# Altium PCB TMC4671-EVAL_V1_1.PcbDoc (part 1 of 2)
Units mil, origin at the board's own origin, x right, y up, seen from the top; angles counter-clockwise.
Board outline 2165.36 x 3346.46 mil, 6 copper layers (Top, GND1, MID, VM, GND2, Bottom), stack 61.733 mil thick; 157 components, 127 nets, 622 pads, 423 vias.
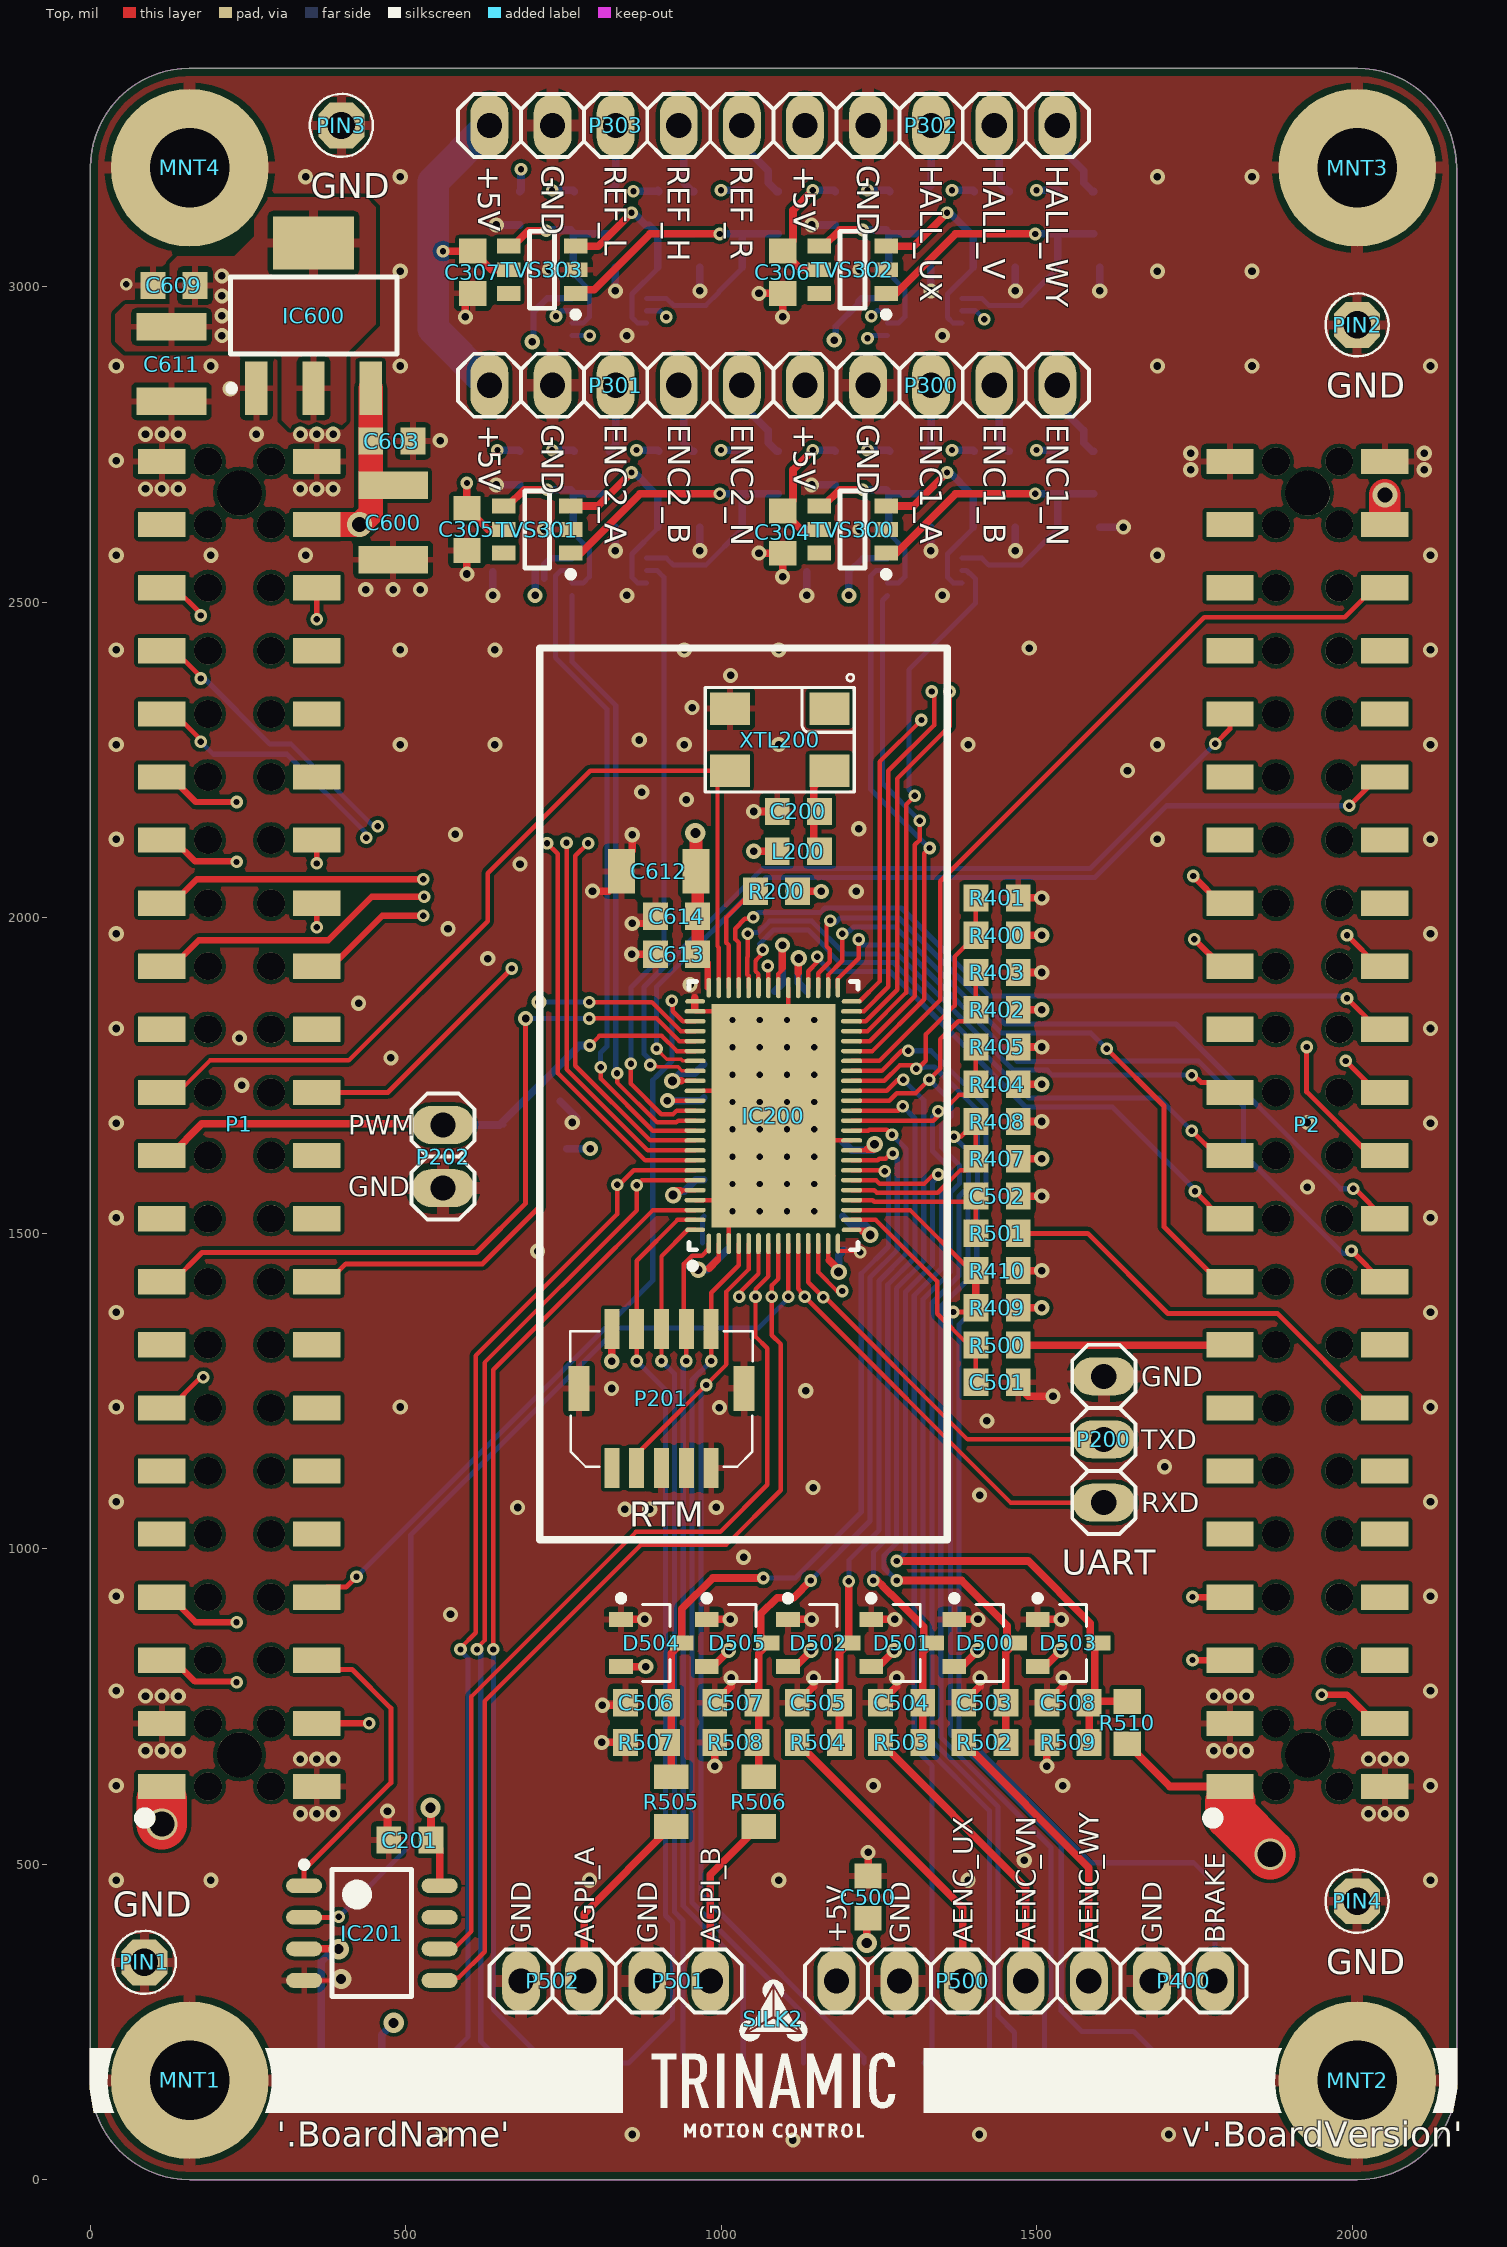
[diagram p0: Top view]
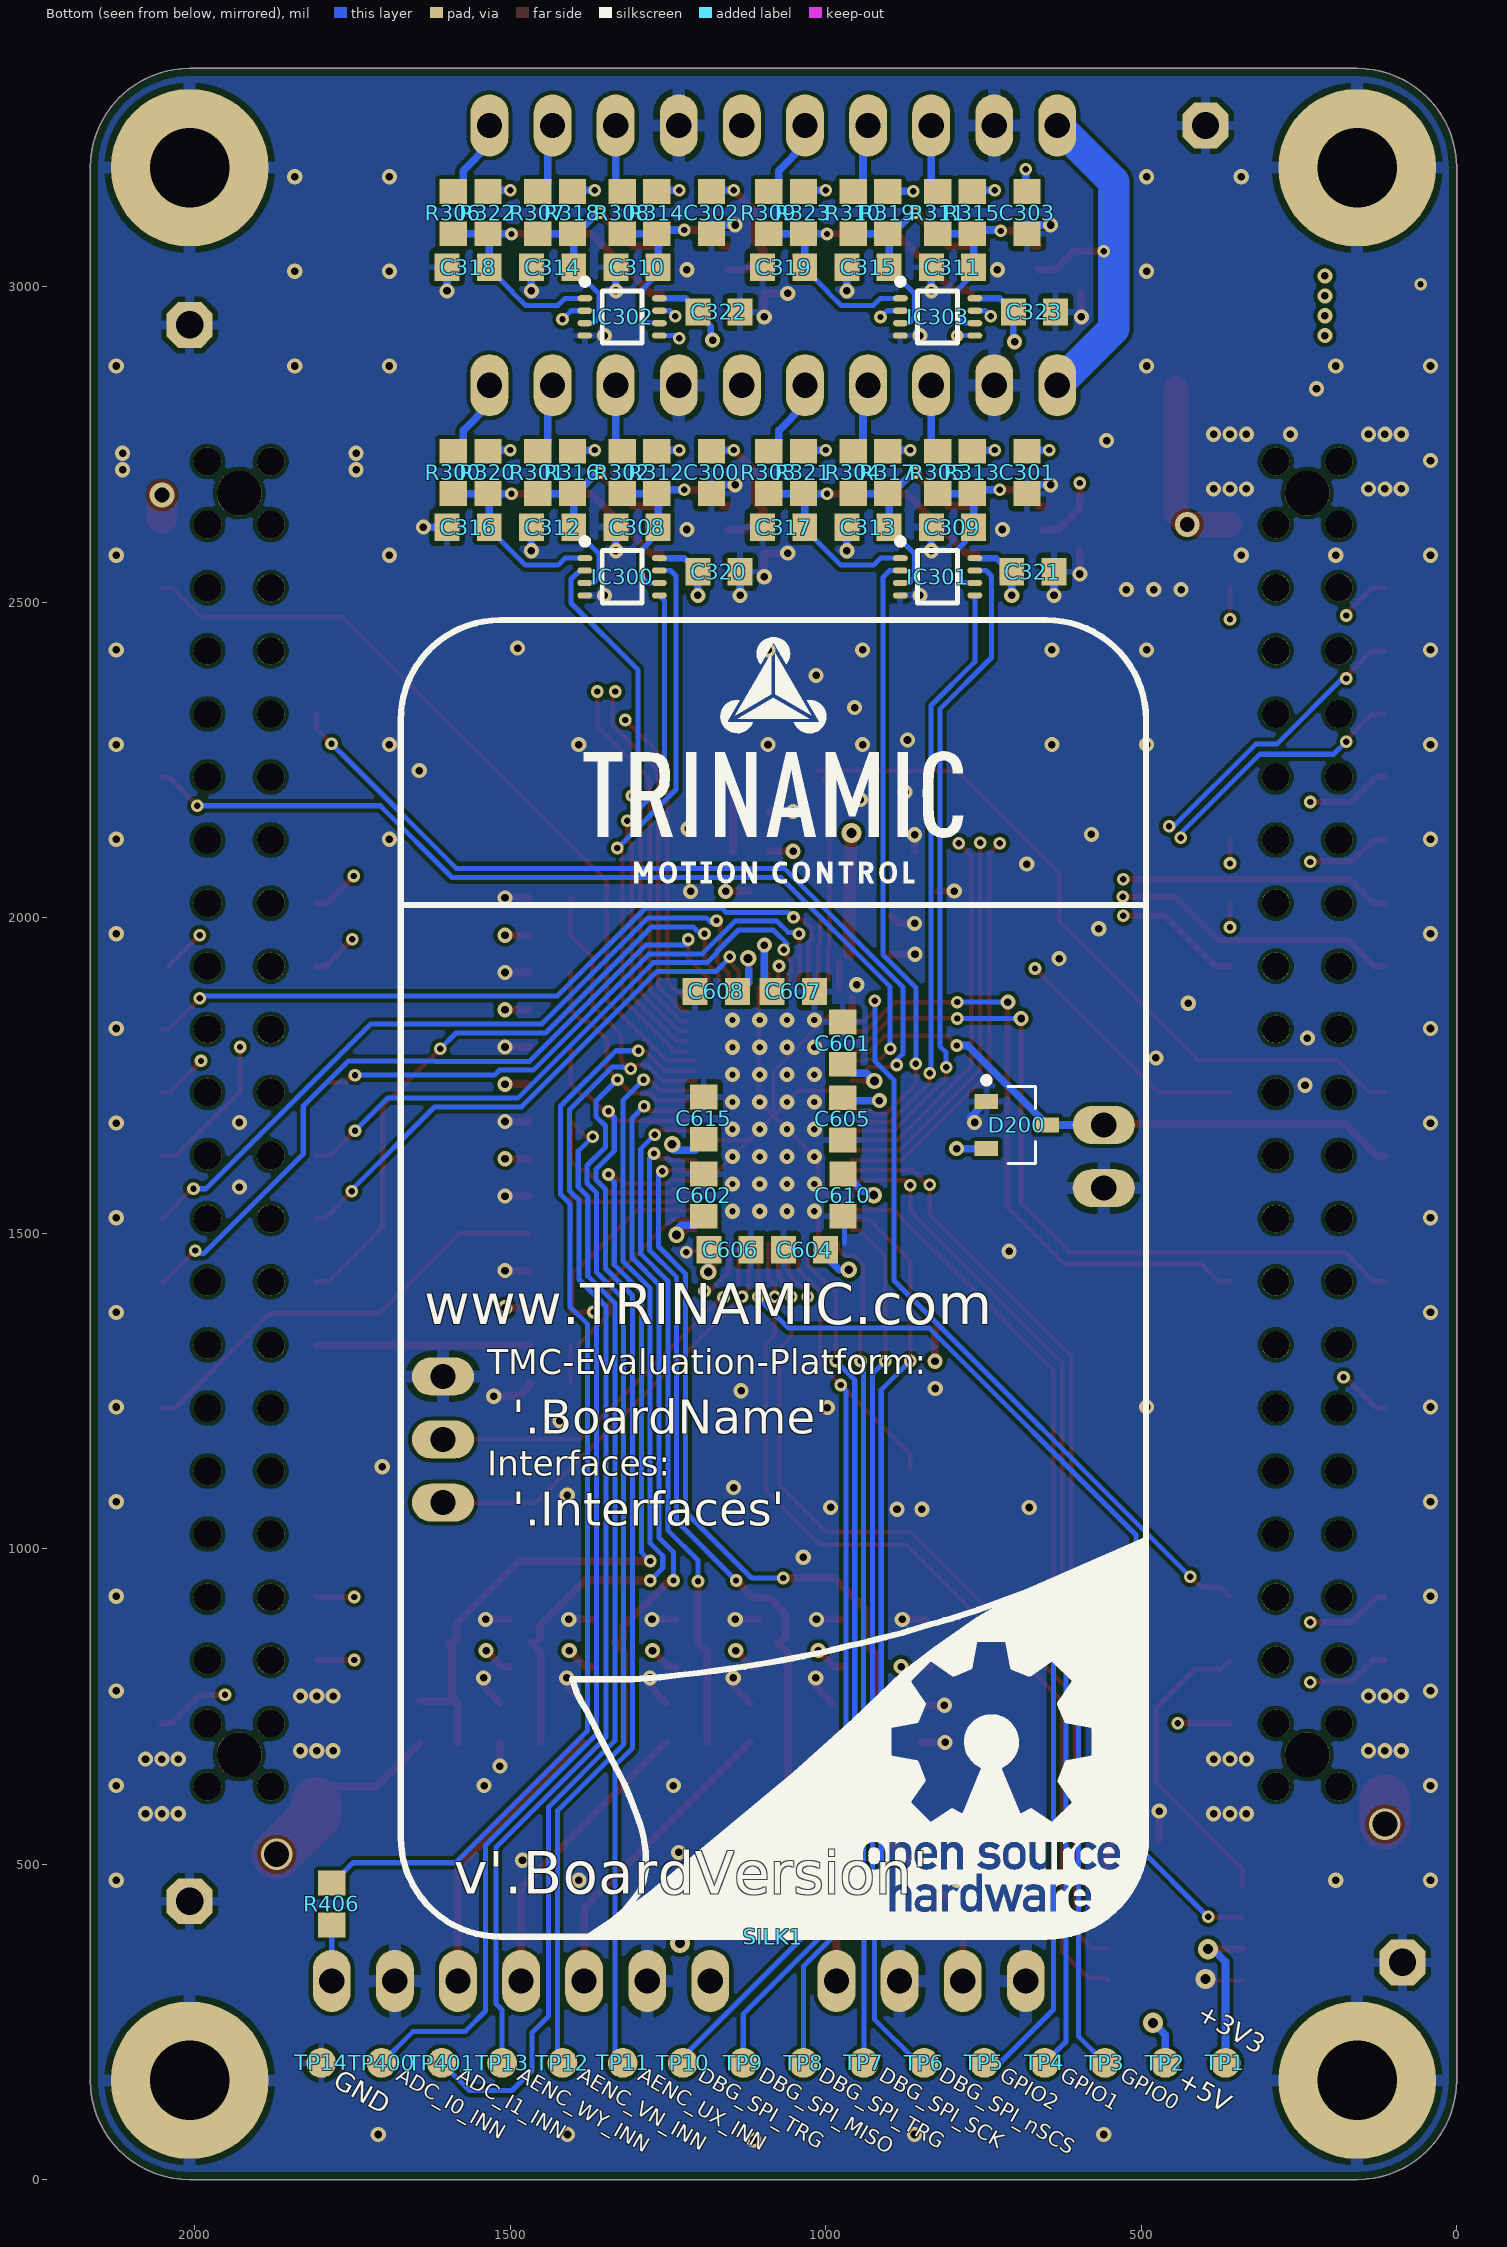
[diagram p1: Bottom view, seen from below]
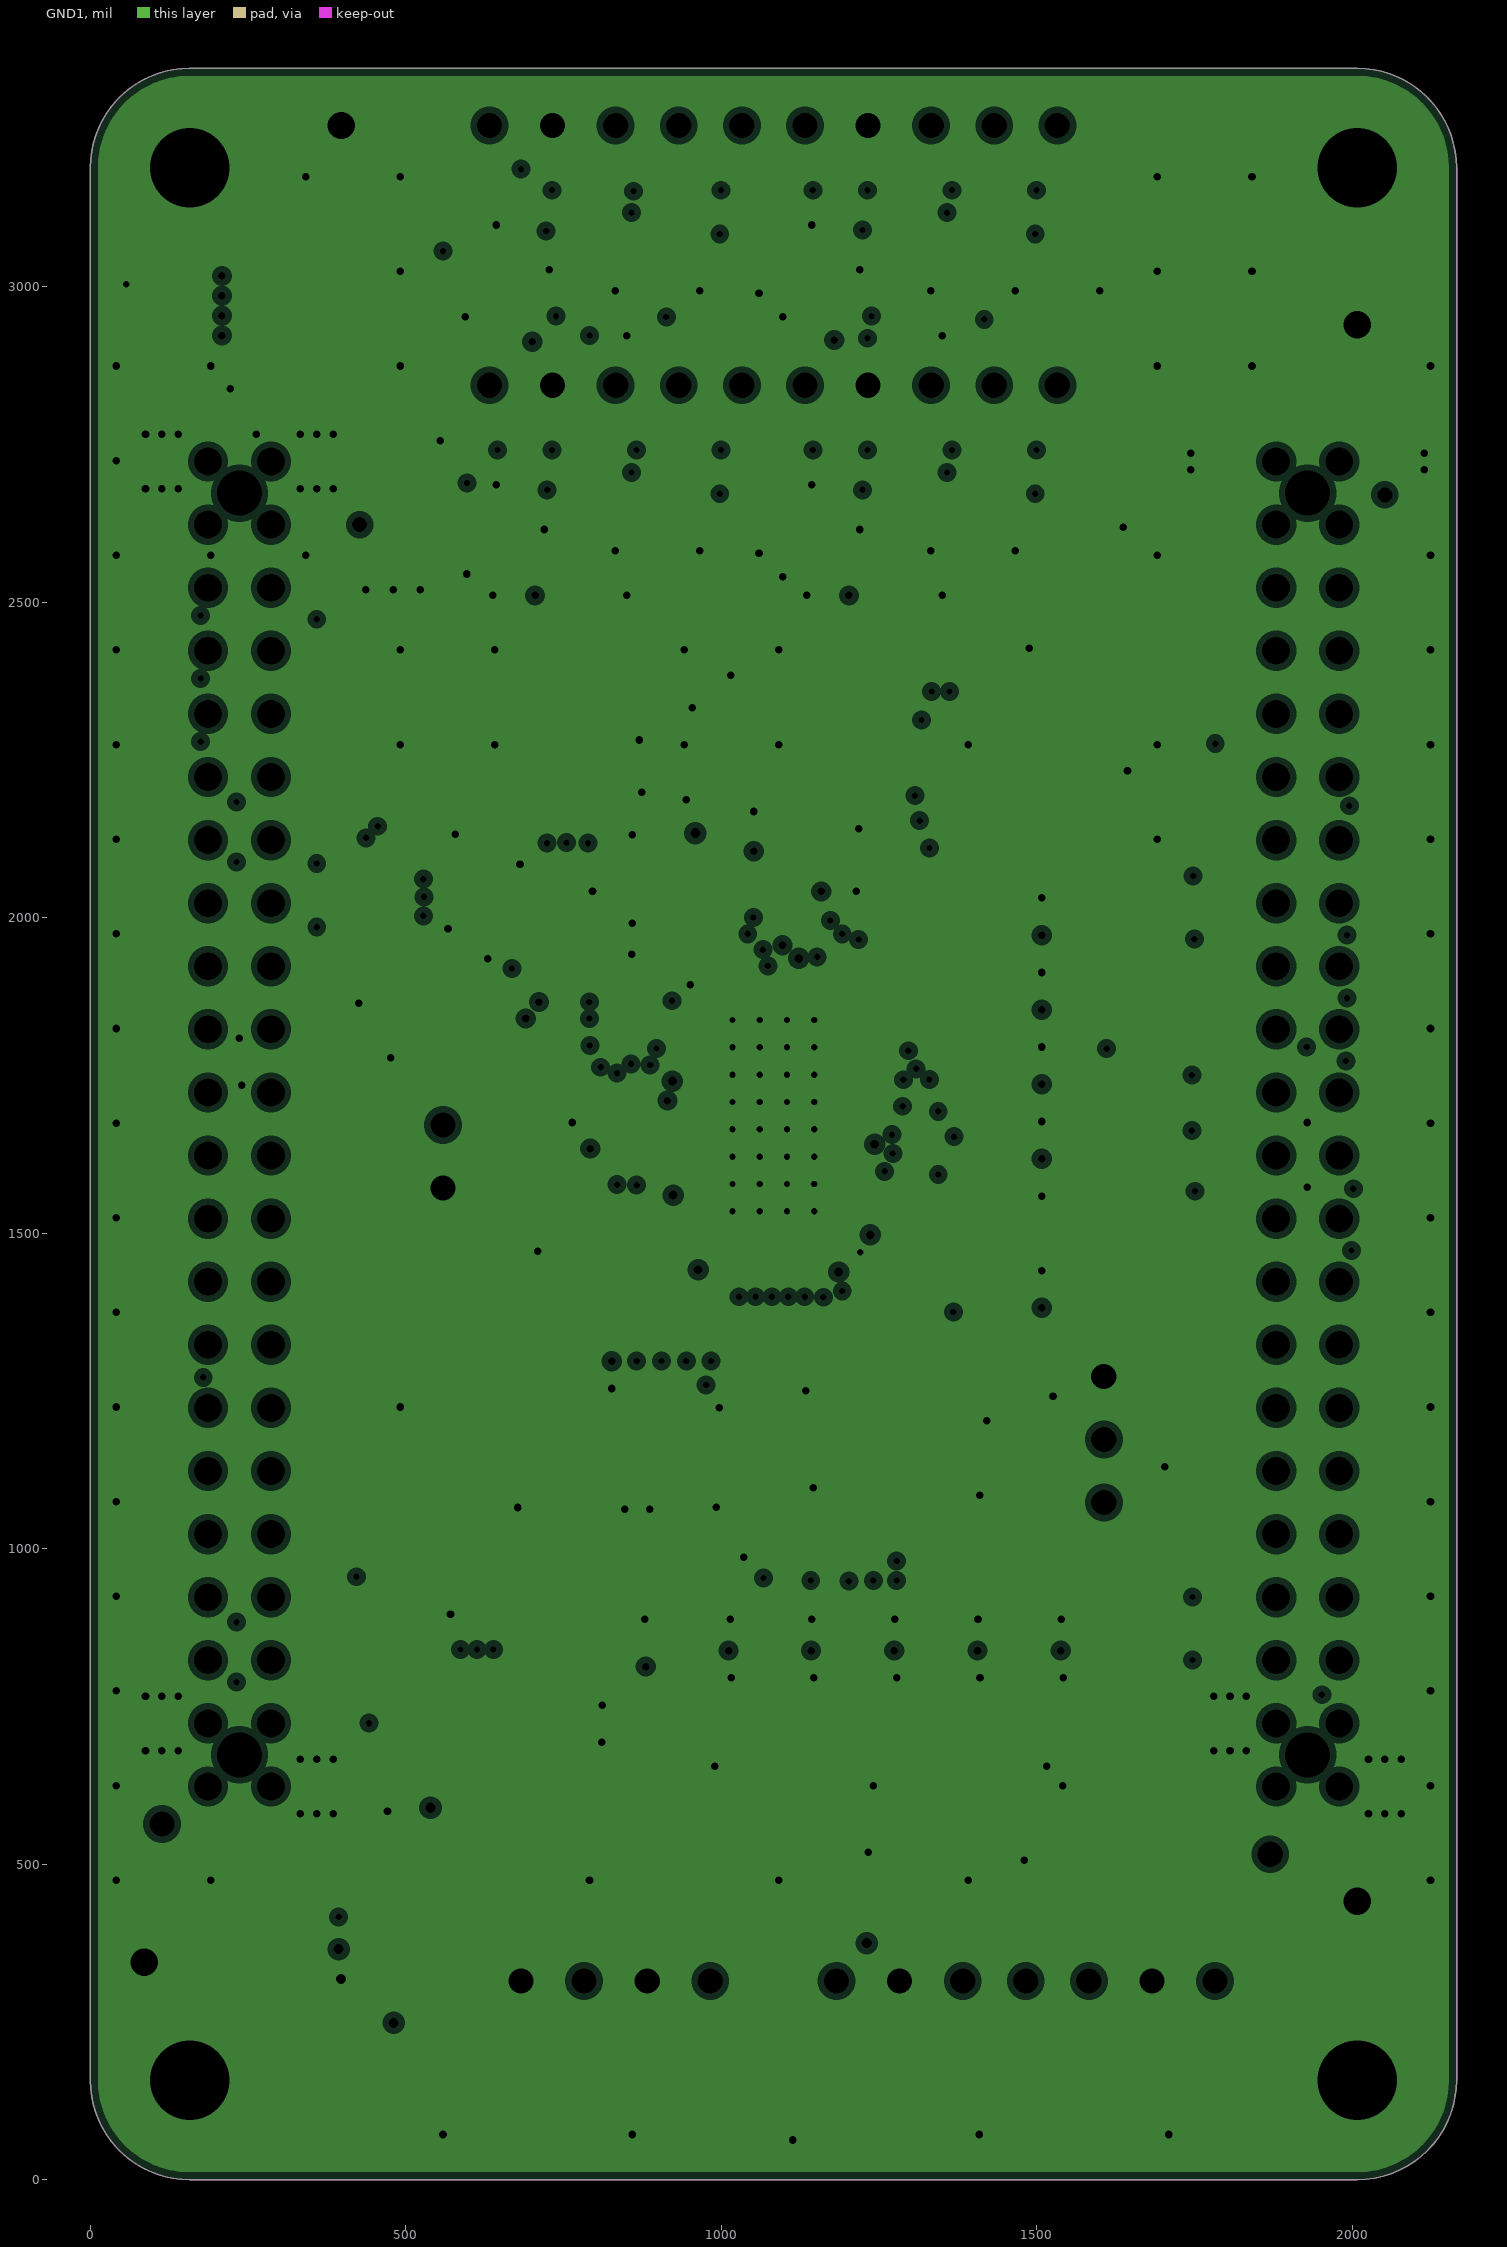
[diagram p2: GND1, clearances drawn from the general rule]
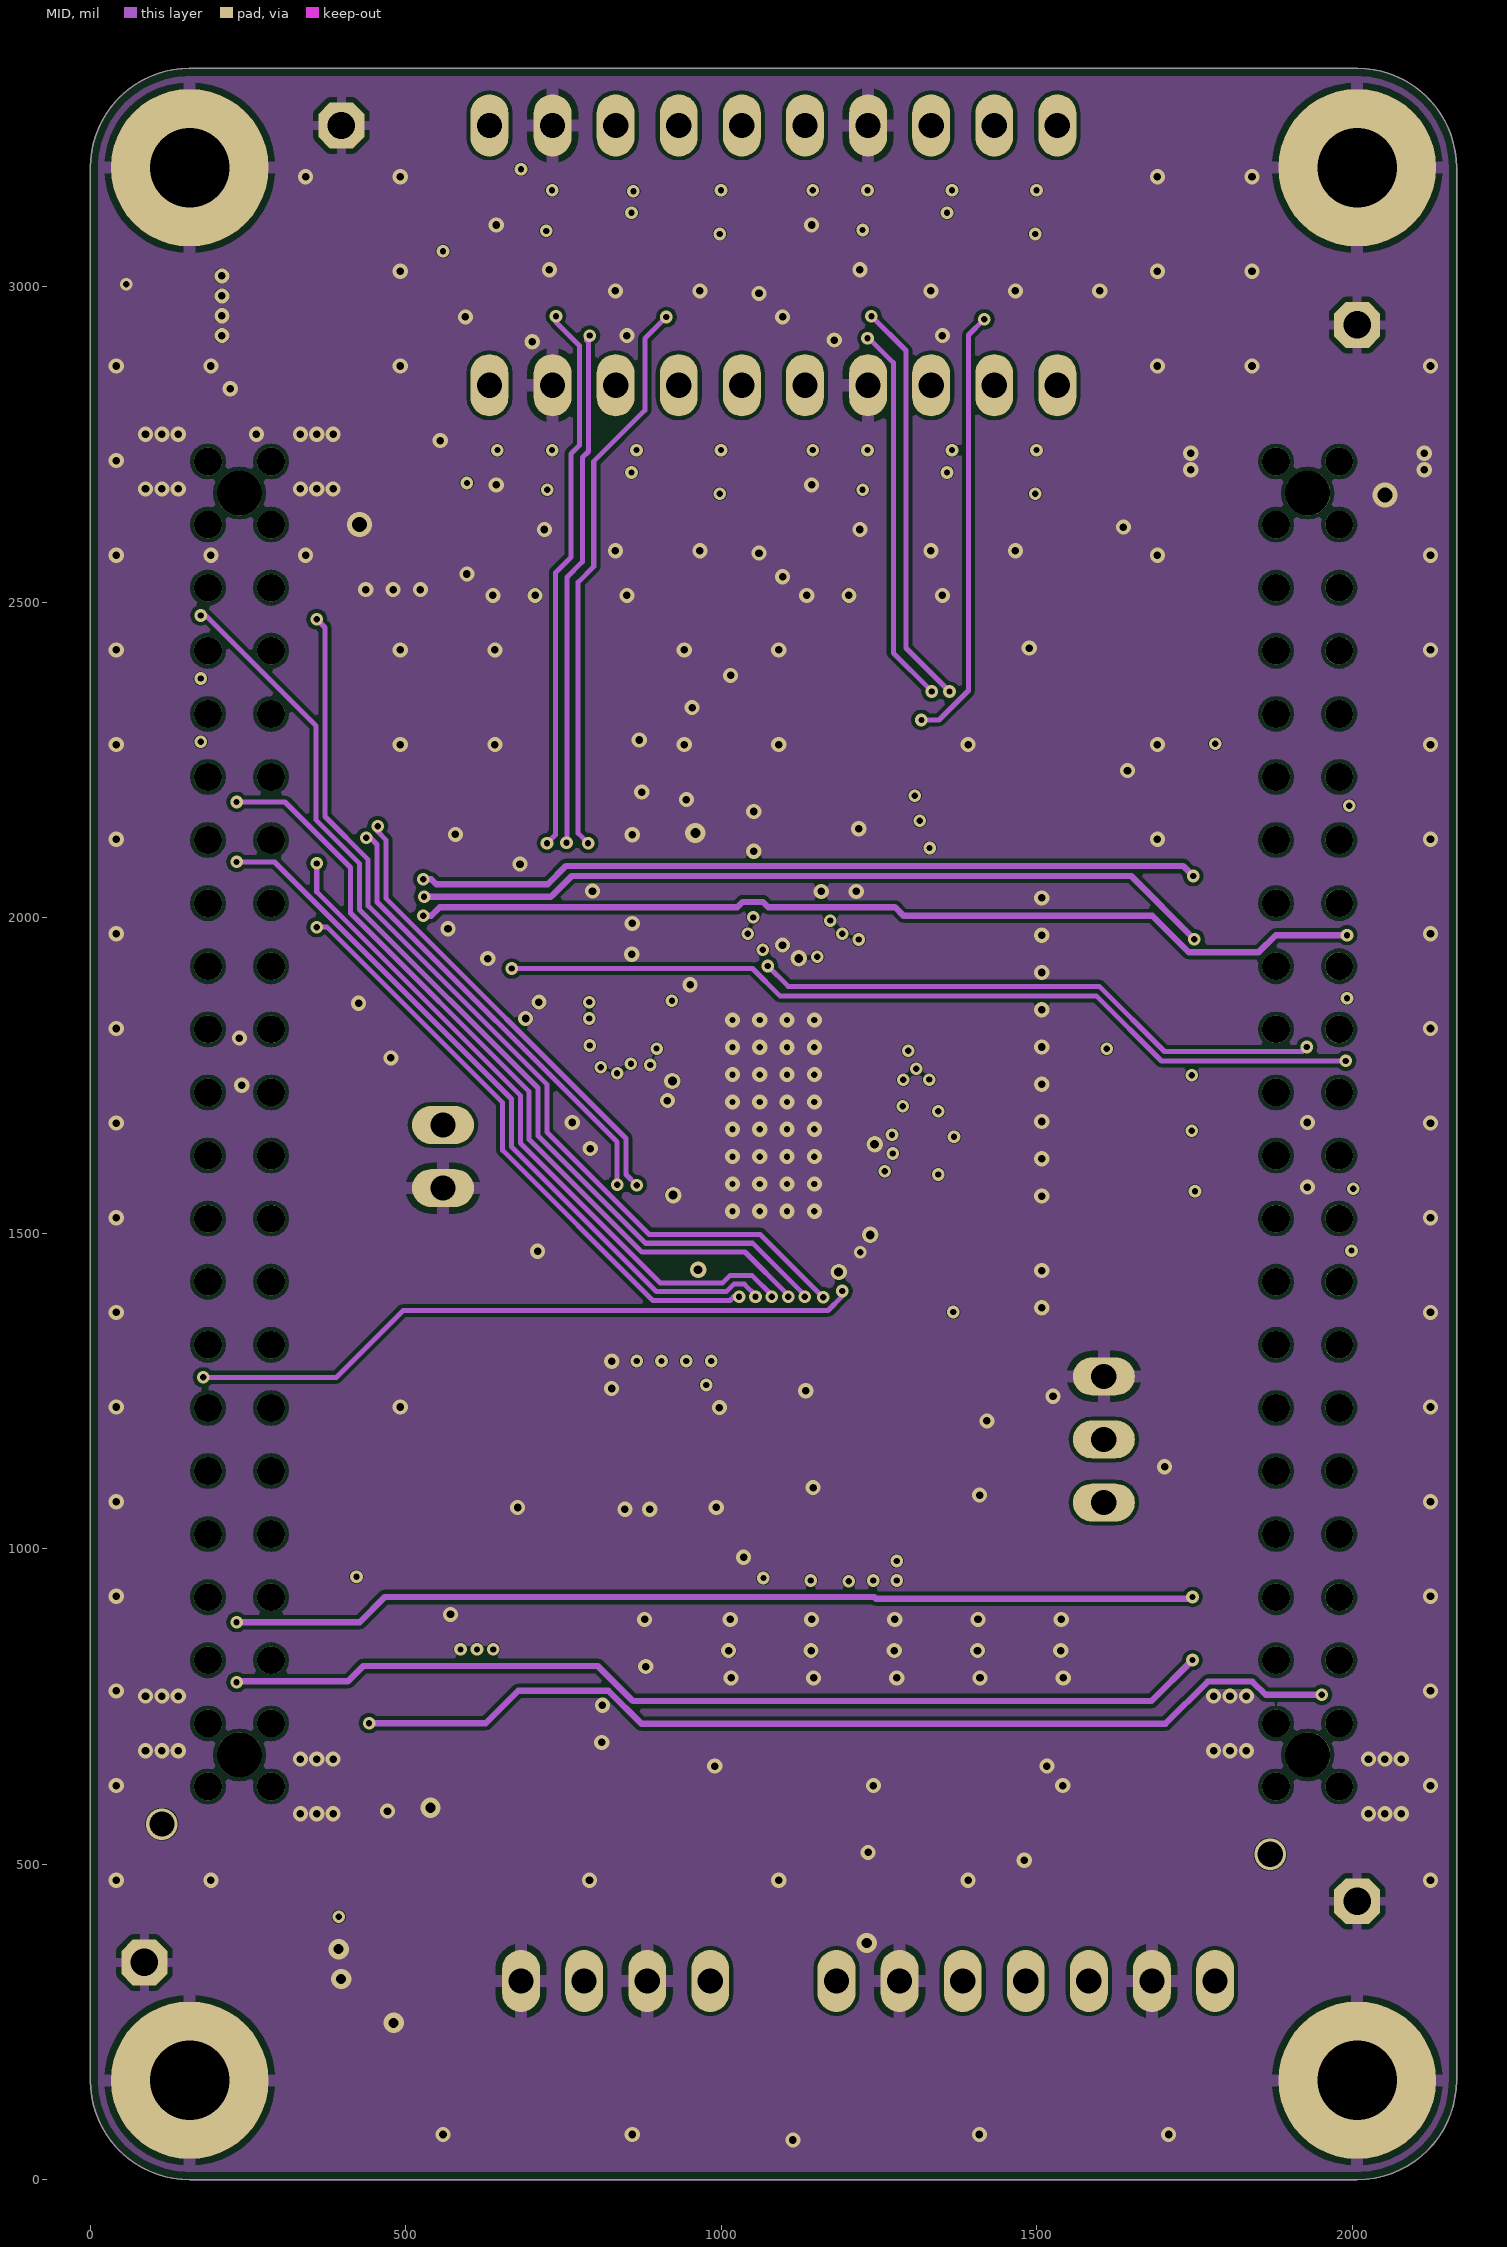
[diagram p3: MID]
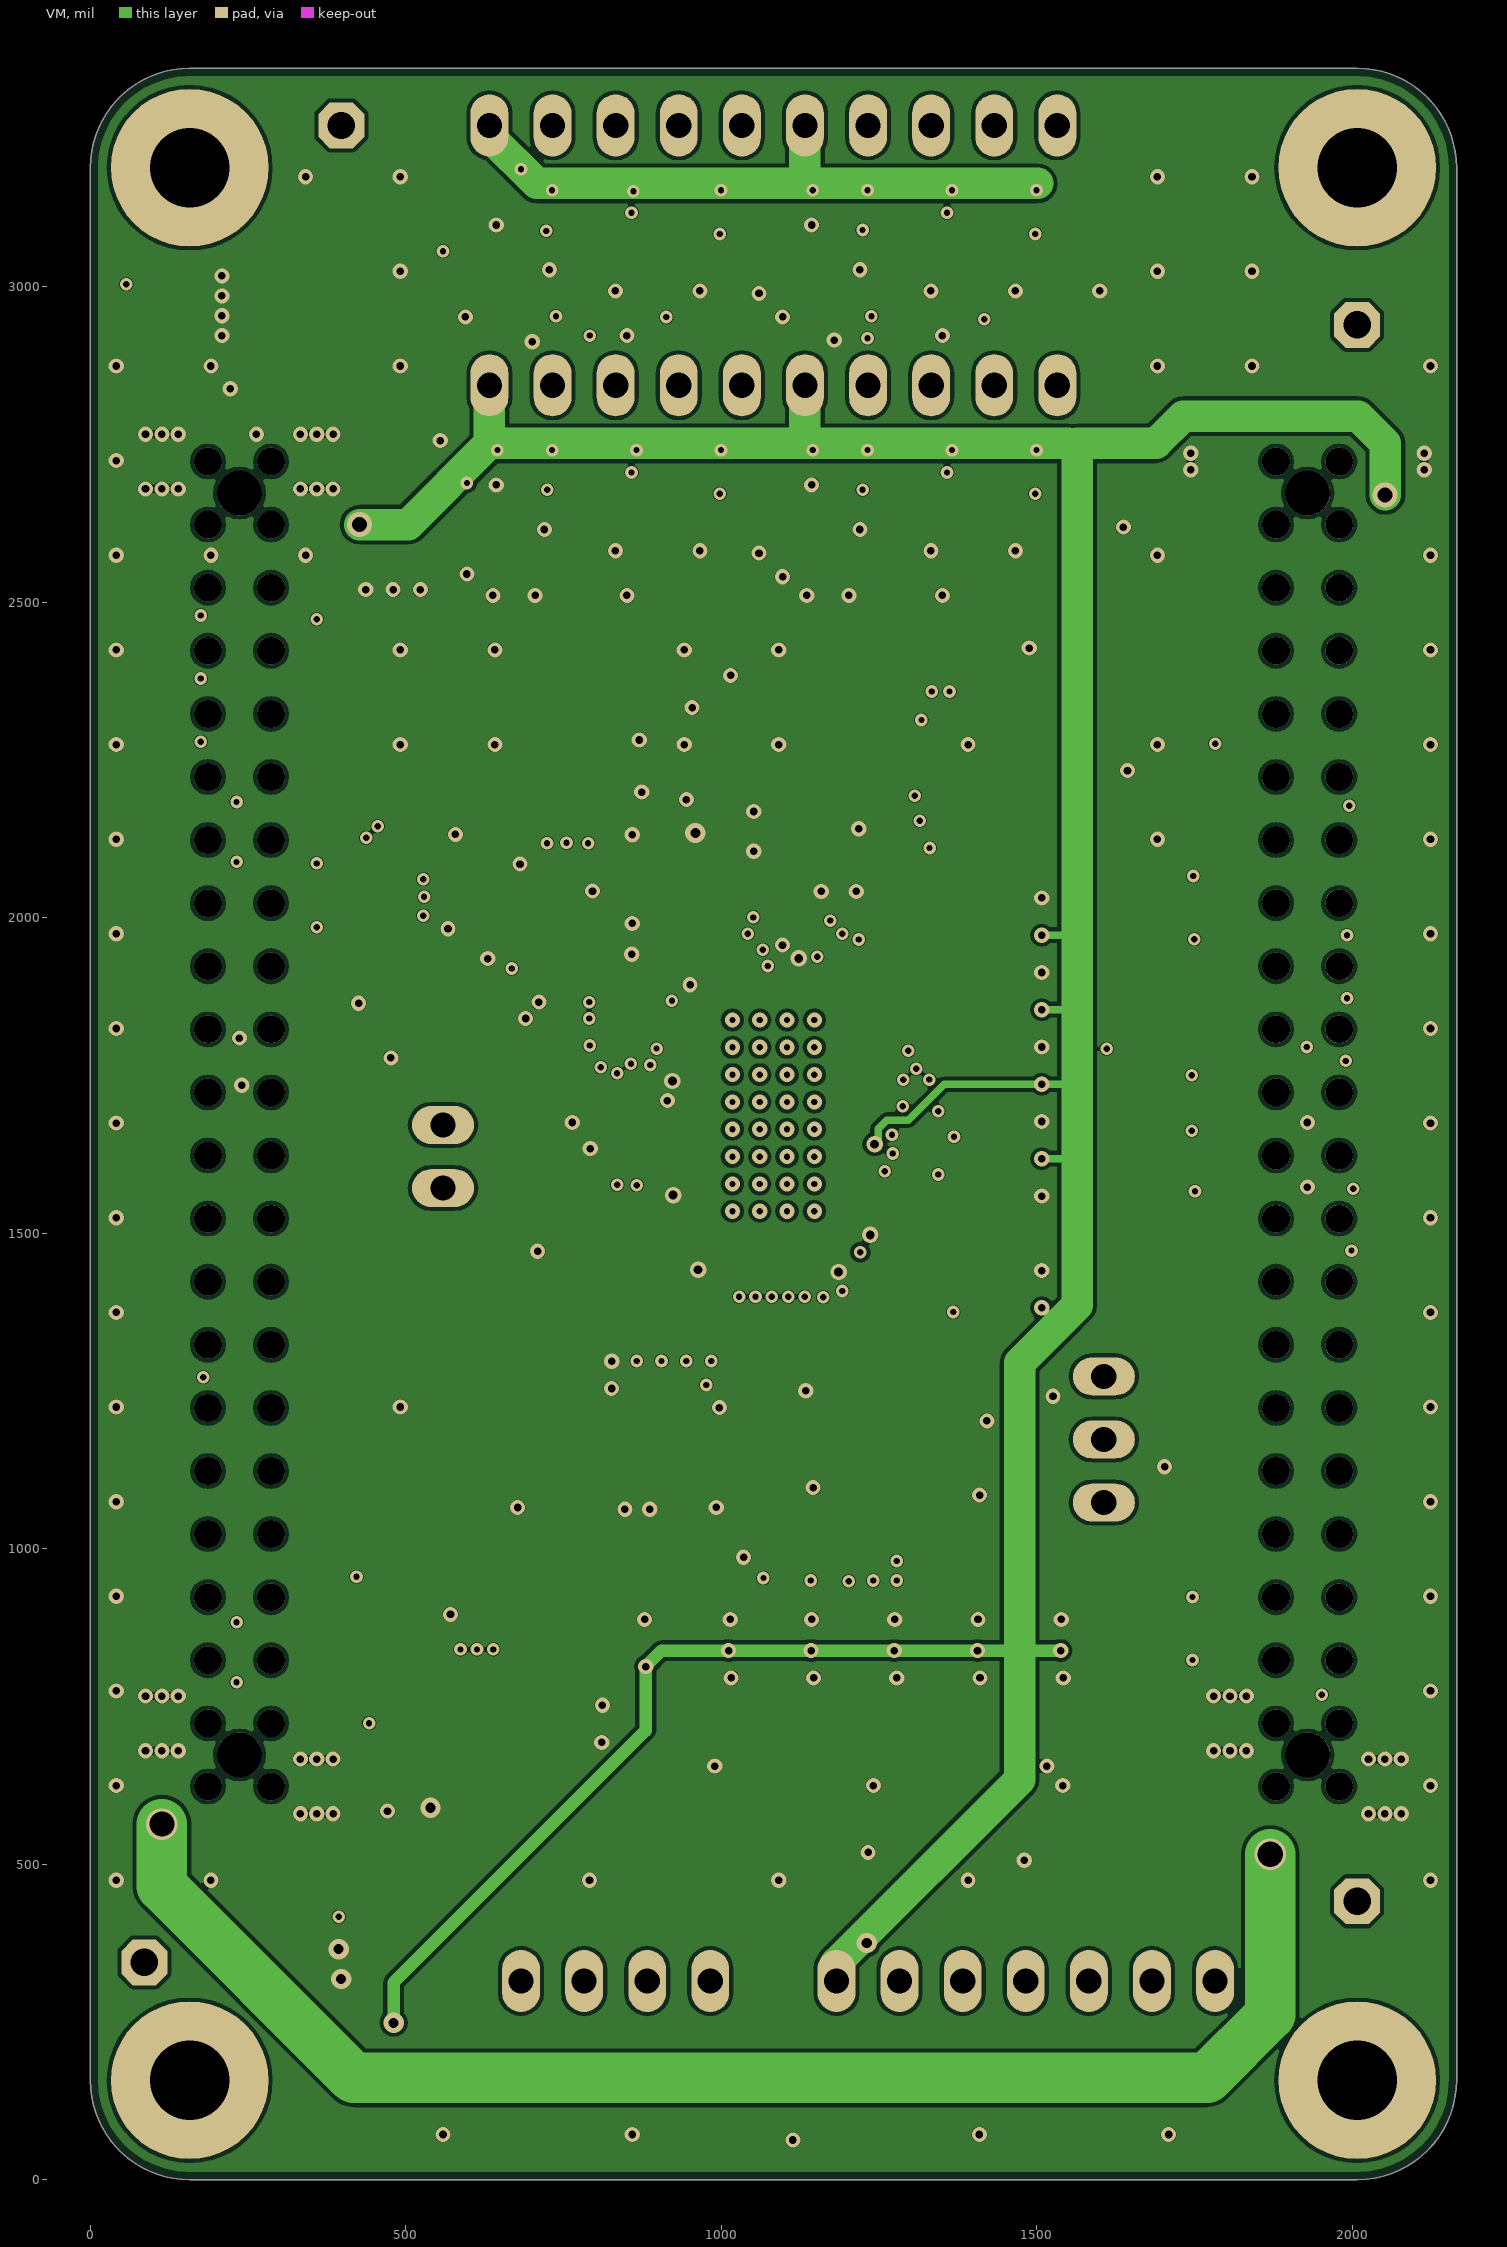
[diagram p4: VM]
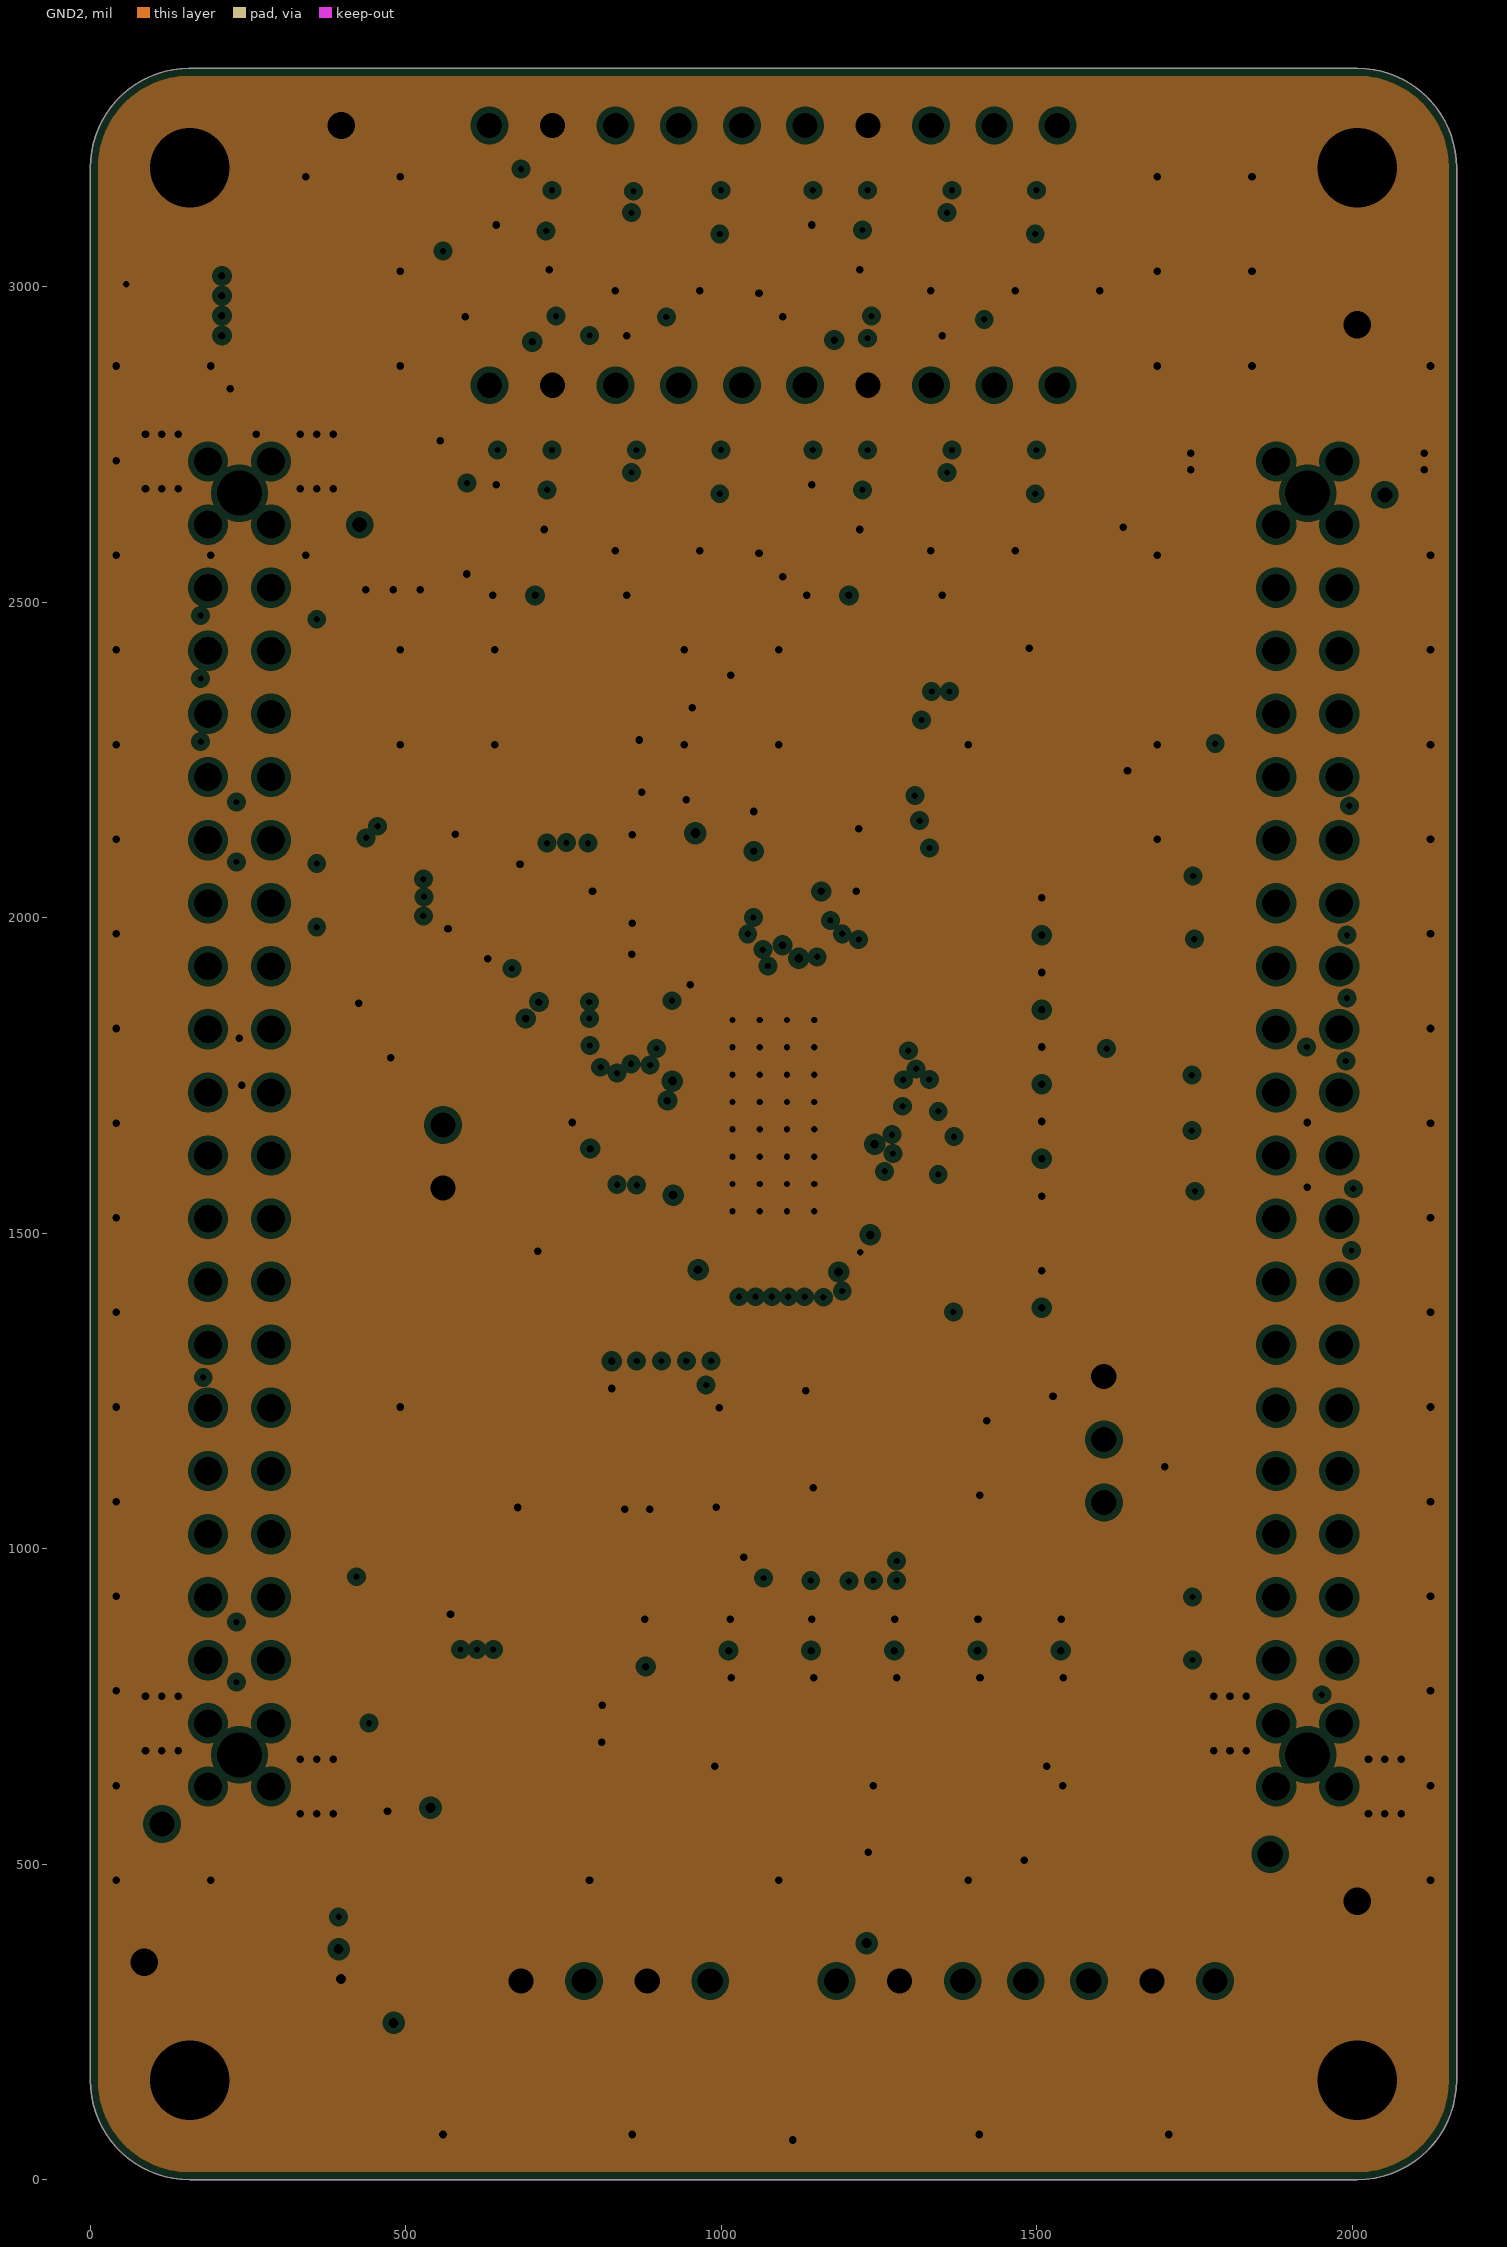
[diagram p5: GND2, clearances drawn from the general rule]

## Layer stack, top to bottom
Top Solder: solder mask 0.4, Solder Resist, Dk 3.5
Top: signal copper 1.378
Dielectric 1: core 5, FR-4, Dk 4.8
GND1: plane copper 1.378, net GND
Dielectric 6: prepreg 5, Dk 4.2
MID: signal copper 1.378
Dielectric 7: core 33.465, Dk 4.2
VM: signal copper 1.378
Dielectric 8: prepreg 5, Dk 4.2
GND2: plane copper 1.378, net GND
Dielectric 5: core 5, Dk 4.2
Bottom: signal copper 1.378
Bottom Solder: solder mask 0.4, Solder Resist, Dk 3.5

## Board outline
0,157.48 0,3188.98 cw(c157.48,3188.98) 157.48,3346.46 2007.87,3346.46 cw(c2007.88,3188.98) 2165.35,3188.98 2165.35,157.48 cw(c2007.87,157.48) 2007.87,0 157.48,0 cw(c157.48,157.48)

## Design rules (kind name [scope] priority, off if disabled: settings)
Clearance Clearance_1 [IsPad and InComponent('IC200')] p1: gap=8.5 ignorepadtopadclearanceinfootprint=TRUE except(6: SMDPad-Via)
Clearance BoardOutlineClearance [OnLayer('Keep-Out Layer')] p2: gap=11.81 ignorepadtopadclearanceinfootprint=FALSE except(6: Via-Fill Via-Poly Via-Region)
Clearance "Fiducial Clearance" [HasFootprint('FIDUCIAL_40MIL')] p3: gap=25.98 ignorepadtopadclearanceinfootprint=TRUE except(0: Arc-Hole Track-Hole SMDPad-Hole THPad-Hole Via-Hole Fill-Hole Poly-Hole Region-Hole Text-Hole)
Clearance [All] p4: gap=6 ignorepadtopadclearanceinfootprint=TRUE except(0: Arc-Hole Track-Hole SMDPad-Hole THPad-Hole Via-Hole Fill-Hole Poly-Hole Region-Hole Text-Hole)
ComponentClearance [All] p1: gap=0 collisioncheckmode=3 verticalgap=100000 showdistances=FALSE
DiffPairsRouting [InDifferentialPairClass('ECAT_DIFFERENTIAL')] p1 off: maxlimit=10 minlimit=7.5 mostfreqgap=10 toplayer_prefgap=7.5 toplayer_minwidth=7.5 toplayer_maxwidth=7.5 toplayer_prefwidth=7.5 midlayer1_prefgap=7.5 midlayer1_minwidth=7.5 midlayer1_maxwidth=7.5 midlayer1_prefwidth=7.5 midlayer2_mingap=10 midlayer2_minwidth=15 midlayer2_maxwidth=15 midlayer2_prefwidth=15 bottomlayer_prefgap=7.5 bottomlayer_minwidth=7.5 bottomlayer_maxwidth=7.5 bottomlayer_prefwidth=7.5 maxuncoupledlength=200
Height [All] p1: minheight=0 maxheight=472.44 prefheight=472.44
HoleSize [All] p1: absolutevalues=TRUE maxlimit=100000 minlimit=9.84 maxpercent=80.000 minpercent=20.000
HoleToHoleClearance [All] p1: gap=12 allowstackedmicrovias=FALSE
MinimumAnnularRing MinimumAnnualRing [OnOutside] p1: minimumring=12
MinimumSolderMaskSliver [All] p1 off: minsoldermaskwidth=1.5
PasteMaskExpansion TestPadPasteMaskExpansion [HasFootprint('SMD_TP_2X2_ROUND')] p1: expansion=-78.74
PasteMaskExpansion [All] p2: expansion=0
PlaneClearance [All] p1: clearance=10
PlaneConnect [All] p1: pad.planeconnectstyle=Relief pad.reliefexpansion=12 pad.reliefentries=4 pad.reliefconductorwidth=10 pad.reliefairgap=10 via.planeconnectstyle=Direct via.reliefexpansion=20 via.reliefentries=4 via.reliefconductorwidth=10 via.reliefairgap=10
PolygonConnect PolygonConnect_1 [IsVia AND InNet('GND')] p1: connectstyle=Direct reliefconductorwidth=10 reliefentries=4 polygonreliefangle="90 Angle" airgapwidth=10
PolygonConnect Large_Pad_PolygonConnect [PadXSize_AllLayers > 90] p2: thpad.connectstyle=Relief thpad.reliefconductorwidth=20 thpad.reliefentries=4 thpad.polygonreliefangle="90 Angle" thpad.airgapwidth=10 smdpad.connectstyle=Relief smdpad.reliefconductorwidth=15 smdpad.reliefentries=4 smdpad.polygonreliefangle="90 Angle" smdpad.airgapwidth=8 via.connectstyle=Direct via.reliefconductorwidth=20 via.reliefentries=4 via.polygonreliefangle="90 Angle" via.airgapwidth=12
PolygonConnect [All] p3: thpad.connectstyle=Relief thpad.reliefconductorwidth=15 thpad.reliefentries=4 thpad.polygonreliefangle="90 Angle" thpad.airgapwidth=8 smdpad.connectstyle=Relief smdpad.reliefconductorwidth=10 smdpad.reliefentries=4 smdpad.polygonreliefangle="90 Angle" smdpad.airgapwidth=8 via.connectstyle=Direct via.reliefconductorwidth=15 via.reliefentries=4 via.polygonreliefangle="90 Angle" via.airgapwidth=8
RoutingVias +VM_RoutingVias [InNet('+VM')] p1: holewidth=40 width=59.06 viastyle="Through Hole" minholewidth=12 minwidth=24 maxholewidth=40 maxwidth=50
RoutingVias [All] p2: holewidth=10 width=20 viastyle="Through Hole" minholewidth=9.84 minwidth=17.72 maxholewidth=16 maxwidth=32
ShortCircuit [All] p1 off: allowed=FALSE
SilkToBoardRegionClearance [All] p1 off:
SilkToSilkClearance [All] p1 off: silktosilkclearance=10
SilkToSolderMaskClearance [IsPad] p1 off: minsilkscreentomaskgap=5 clearancetoexposedcopper=TRUE
SolderMaskExpansion FiducialSolderMaskExpansion [HasFootprint('FIDUCIAL_40MIL')] p1: expansion=26
SolderMaskExpansion [All] p2: expansion=4
UnRoutedNet [All] p1 off:
Width +VM_width [InNet('+VM')] p1: maxlimit=100 minlimit=12 preferedwidth=80
Width TMC461_Room_Width [WithinRoom('RoomDefinition') and OnTop] p2: maxlimit=8 minlimit=8 preferedwidth=8
Width Main_Routing_Width [All] p3: maxlimit=500 minlimit=6 preferedwidth=11.81
16 further rules are at their usual default settings.

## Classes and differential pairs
component class [6]_PSU: C600 C601 C602 C603 C604 C605 C606 C607 C608 C609 C610 C611 C612 C613 C614 C615 IC200 IC600
component class [4]_Output_Feedback_2: P400 R400 R401 R402 R403 R404 R405 R406 R407 R408 R409 R410 TP400 TP401
component class [3]_Output_Feedback: C300 C301 C302 C303 C304 C305 C306 C307 C308 C309 C310 C311 C312 C313 C314 C315 C316 C317 C318 C319 C320 C321 C322 C323 IC300 IC301 IC302 IC303 P300 P301 P302 P303 R300 R301 R302 R303 R304 R305 R306 R307 R308 R309 R310 R311 R312 R313 R314 R315 R316 R317 R318 R319 R320 R321 R322 R323 TVS300 TVS301 TVS302 TVS303
component class [2]_Communication_Inputs: C200 C201 C202 D200 IC201 L200 P200 P201 P202 P207 R200 XTL200
differential pair class ECAT_DIFF: R0 R1 RD0 RD1 T0 T1 TD0 TD1
component class [1]_InterfaceConnectors: MNT1 MNT2 MNT3 MNT4 P1 P2 PIN1 PIN2 PIN3 PIN4 SILK1 SILK2 TP1 TP2 TP3 TP4 TP5 TP6 TP7 TP8 TP9 TP10 TP11 TP12 TP13 TP14
component class [5]_Analog_input_filters: C500 C501 C502 C503 C504 C505 C506 C507 C508 D500 D501 D502 D503 D504 D505 P500 P501 P502 R500 R501 R502 R503 R504 R505 R506 R507 R508 R509 R510

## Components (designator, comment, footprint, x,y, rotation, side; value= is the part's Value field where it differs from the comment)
C200 "100nF/10V" C0603 1122.32,2168.52 r180 top
C201 "100nF/10V" C0603 506.51,538.36 r0 top
C300 "1uF/10V" C0603 1180.71,2705.91 r90 bottom
C301 "1uF/10V" C0603 680.71,2705.91 r90 bottom
C302 "1uF/10V" C0603 1180.71,3117.72 r90 bottom
C303 "1uF/10V" C0603 680.71,3117.72 r90 bottom
C304 "100nF/10V" C0603 1097.24,2611.42 r270 top
C305 "100nF/10V" C0603 596.94,2615.76 r270 top
C306 "100nF/10V" C0603 1097.24,3023.23 r270 top
C307 "100nF/10V" C0603 606.3,3023.23 r270 top
C308 "100pF/50V/5%" C0603 1298.82,2619.29 r180 bottom
C309 "100pF/50V/5%" C0603 798.82,2619.29 r180 bottom
C310 "100pF/50V/5%" C0603 1298.82,3031.1 r180 bottom
C311 "100pF/50V/5%" C0603 798.82,3031.1 r180 bottom
C312 "100pF/50V/5%" C0603 1432.68,2619.29 r180 bottom
C313 "100pF/50V/5%" C0603 932.68,2619.29 r180 bottom
C314 "100pF/50V/5%" C0603 1432.68,3031.1 r180 bottom
C315 "100pF/50V/5%" C0603 932.68,3031.1 r180 bottom
C316 "100pF/50V/5%" C0603 1566.54,2619.29 r180 bottom
C317 "100pF/50V/5%" C0603 1066.54,2619.29 r180 bottom
C318 "100pF/50V/5%" C0603 1566.54,3031.1 r180 bottom
C319 "100pF/50V/5%" C0603 1066.54,3031.1 r180 bottom
C320 "100nF/10V" C0603 1168.9,2548.43 r0 bottom
C321 "100nF/10V" C0603 671.45,2548.43 r0 bottom
C322 "100nF/10V" C0603 1168.9,2960.24 r0 bottom
C323 "100nF/10V" C0603 668.9,2960.24 r0 bottom
C500 "1uF/10V" C0603 1232.68,447.96 r270 top
C501 "100pF/50V/5%" C0603 1437.17,1263.78 r180 top
C502 "100pF/50V/5%" C0603 1437.17,1559.06 r180 top
C503 "100pF/50V/5%" C0603 1417.8,756.03 r0 top
C504 "100pF/50V/5%" C0603 1285.91,756.03 r0 top
C505 "100pF/50V/5%" C0603 1154.02,756.03 r0 top
C506 "100pF/10V" C0603 881.5,756.03 r0 top
C507 "100pF/10V" C0603 1023.23,756.03 r0 top
C508 "10nF" C0603 1549.68,756.03 r0 top
C600 "100uF/16V" C1210 479.84,2626.46 r90 top
C601 "100nF/10V" C0603 972.68,1801.34 r270 bottom
C602 "100nF/10V" C0603 1192.91,1560.52 r270 bottom
C603 "4u7/10V" C0603 477.88,2755.65 r180 top
C604 "100nF/10V" C0603 1033.31,1473.9 r180 bottom
C605 "100nF/10V" C0603 972.68,1681.34 r90 bottom
C606 "100nF/10V" C0603 1151.42,1473.9 r0 bottom
C607 "100nF/10V" C0603 1051.18,1883.35 r0 bottom
C608 "100nF/10V" C0603 1173.23,1883.35 r180 bottom
C609 "4u7/10V" C0603 132.63,3002.23 r0 top
C610 "100nF/10V" C0603 972.44,1560.52 r90 bottom
C611 "100uF/6V3" C1210 128.74,2877.64 r90 top
C612 "47uF/10V" C1206 900.9,2073.62 r0 top
C613 "100nF" C0603 929.1,1942.37 r0 top
C614 "470nF" C0603 929.1,2002.37 r180 top
C615 "4u7" C0603 1192.91,1682.56 r270 bottom
D200 "BAT54S" SOT95P237X130-3N 696.85,1671.65 r180 bottom
D500 "BAT54S" SOT95P237X130-3N 1417.8,850.69 r0 top
D501 "BAT54S" SOT95P237X130-3N 1285.91,850.69 r0 top
D502 "BAT54S" SOT95P237X130-3N 1154.02,850.69 r0 top
D503 "BAT54S" SOT95P237X130-3N 1549.68,850.69 r0 top
D504 "BAT54S" SOT95P237X130-3N 889.37,850.69 r0 top
D505 "BAT54S" SOT95P237X130-3N 1025.2,850.69 r0 top
IC200 "TMC4671" QFN40P1050X650X90_HS-77N 1082.68,1686.5 r90 top
IC201 "AT25128B-SSHL-T" SOP127P600X175-8N 446.29,390.94 r0 top
IC300 "SN74LVC3G17DCUR" TSSOP50P310X90-8L 1322.44,2540.55 r180 bottom
IC301 "SN74LVC3G17DCUR" TSSOP50P310X90-8L 822.44,2540.55 r180 bottom
IC302 "SN74LVC3G17DCUR" TSSOP50P310X90-8L 1322.44,2952.36 r180 bottom
IC303 "SN74LVC3G17DCUR" TSSOP50P310X90-8L 822.44,2952.36 r180 bottom
IC600 "LD1117S33CTR" SOT230P700X180-4N 353.86,2954.41 r90 top
L200 "30R" L0603 1122.32,2105.53 r0 top
MNT1 "MOUNTING_HOLE" MNT_HOLE_6.35-3.2 157.48,157.48 r0 top
MNT2 "MOUNTING_HOLE" MNT_HOLE_6.35-3.2 2007.87,157.48 r0 top
MNT3 "MOUNTING_HOLE" MNT_HOLE_6.35-3.2 2007.87,3188.98 r0 top
MNT4 "MOUNTING_HOLE" MNT_HOLE_6.35-3.2 157.48,3188.98 r0 top
P1 "Interface to UC/MC" Interface_Connector 236.22,1673.23 r90 top locked
P2 "Interface to UC/MC" Interface_Connector 1929.13,1673.23 r90 top locked
P200 "UART" TH_HDR_1X3 1606.41,1173.23 r270 top
P201 "DF20F-10DP-1V(56)" "CON, TMC Debug SPI" 905.32,1238.23 r0 top
P202 "PWM_IN" TH_HDR_1X2 559.06,1621.65 r270 top
P300 "ENC1" TH_HDR_1X5 1332.68,2844.1 r180 top
P301 "ENC2" TH_HDR_1X5 832.68,2844.1 r180 top
P302 "HALL" TH_HDR_1X5 1332.68,3255.91 r180 top
P303 "REF_SW" TH_HDR_1X5 832.68,3255.91 r180 top
P400 "BRAKE_OUT" TH_HDR_1X2 1732.68,314.96 r0 top
P500 "AENC" TH_HDR_1X5 1382.68,314.96 r180 top
P501 "AIN_B" TH_HDR_1X2 932.68,314.96 r180 top
P502 "AIN_A" TH_HDR_1X2 732.68,314.96 r180 top
PIN1 "GND" TP_1.1-1.85_OCT 85.68,344.46 r90 top
PIN2 "GND" TP_1.1-1.85_OCT 2007.87,2939.76 r90 top
PIN3 "GND" TP_1.1-1.85_OCT 397.92,3255.91 r90 top
PIN4 "GND" TP_1.1-1.85_OCT 2007.87,441.34 r90 top
R200 "10k" R0603 1087.63,2041.89 r0 top
R300 "22R" R0603 1590.16,2705.91 r90 bottom
R301 "22R" R0603 1456.3,2705.91 r90 bottom
R302 "22R" R0603 1322.44,2705.91 r90 bottom
R303 "22R" R0603 1090.16,2705.91 r90 bottom
R304 "22R" R0603 956.3,2705.91 r90 bottom
R305 "22R" R0603 822.44,2705.91 r90 bottom
R306 "22R" R0603 1590.16,3117.72 r90 bottom
R307 "22R" R0603 1456.3,3117.72 r90 bottom
R308 "22R" R0603 1322.44,3117.72 r90 bottom
R309 "22R" R0603 1090.16,3117.72 r90 bottom
R310 "22R" R0603 956.3,3117.72 r90 bottom
R311 "22R" R0603 822.44,3117.72 r90 bottom
R312 "4k7" R0603 1267.32,2705.91 r90 bottom
R313 "4k7" R0603 767.32,2705.91 r90 bottom
R314 "4k7" R0603 1267.32,3117.72 r90 bottom
R315 "4k7" R0603 767.32,3117.72 r90 bottom
R316 "4k7" R0603 1401.18,2705.91 r90 bottom
R317 "4k7" R0603 901.18,2705.91 r90 bottom
R318 "4k7" R0603 1401.18,3117.72 r90 bottom
R319 "4k7" R0603 901.18,3117.72 r90 bottom
R320 "4k7" R0603 1535.04,2705.91 r90 bottom
R321 "4k7" R0603 1035.04,2705.91 r90 bottom
R322 "4k7" R0603 1535.04,3117.72 r90 bottom
R323 "4k7" R0603 1035.04,3117.72 r90 bottom
R400 "10k" R0603 1437.17,1972.44 r0 top
R401 "10k" R0603 1437.17,2031.5 r180 top
R402 "10k" R0603 1437.17,1854.33 r0 top
R403 "10k" R0603 1437.17,1913.39 r180 top
R404 "10k" R0603 1437.17,1736.22 r0 top
R405 "10k" R0603 1437.17,1795.28 r180 top
R406 "10R" R0603 1782.68,437.06 r90 bottom
R407 "10k" R0603 1437.17,1618.11 r0 top
R408 "10k" R0603 1437.17,1677.17 r180 top
R409 "10k" R0603 1437.17,1381.89 r0 top
R410 "10k" R0603 1437.17,1440.94 r180 top
R500 "100R" R0603 1437.17,1322.83 r0 top
R501 "100R" R0603 1437.17,1500 r0 top
R502 "100R" R0603 1417.8,693.04 r180 top
R503 "100R" R0603 1285.91,693.04 r180 top
R504 "100R" R0603 1154.02,693.04 r180 top
R505 "4k" R0805 920.87,599.41 r270 top
R506 "4k" R0805 1059.45,599.41 r270 top
R507 "1k" R0603 881.5,693.04 r180 top
R508 "1k" R0603 1023.23,693.04 r180 top
R509 "1k5" R0603 1549.68,693.04 r180 top
R510 "100k" R0603 1643.31,724.54 r270 top
SILK1 "BACK SIDE GRAPHICS" TMC4671_EVAL_V1_0_BACK_LABEL 1082.68,385.28 r180 bottom
SILK2 "TMC LOGO SMALL" TMC_logo_small 1082.7,255.22 r0 top
TP1 "+3V3" TP_SMD_1.2MM_ROUND#1 432.68,185.04 r270 bottom
TP2 "+5V" TP_SMD_1.2MM_ROUND#2 461.68,185.04 r270 bottom
TP3 "GPIO0" TP_SMD_1.2MM_ROUND#2 557.22,185.04 r270 bottom
TP4 "GPIO1" TP_SMD_1.2MM_ROUND#2 652.76,185.04 r270 bottom
TP5 "GPIO2" TP_SMD_1.2MM_ROUND#2 748.29,185.04 r270 bottom
TP6 "GPIO3" TP_SMD_1.2MM_ROUND#2 843.83,185.04 r270 bottom
TP7 "GPIO4" TP_SMD_1.2MM_ROUND#2 939.37,185.04 r270 bottom
TP8 "GPIO5" TP_SMD_1.2MM_ROUND#2 1034.91,185.04 r270 bottom
TP9 "GPIO6" TP_SMD_1.2MM_ROUND#2 1130.45,185.04 r270 bottom
TP10 "GPIO7" TP_SMD_1.2MM_ROUND#2 1225.98,185.04 r0 bottom
TP11 "AENC_UX_N" TP_SMD_1.2MM_ROUND#2 1321.52,185.04 r0 bottom
TP12 "AENC_VN_N" TP_SMD_1.2MM_ROUND#2 1417.06,185.04 r0 bottom
TP13 "AENC_WY_N" TP_SMD_1.2MM_ROUND#2 1512.6,185.04 r0 bottom
TP14 "GND" TP_SMD_1.2MM_ROUND#2 1799.21,185.04 r90 bottom
TP400 "ADC_I0_INN" TP_SMD_1.2MM_ROUND#2 1703.67,185.04 r180 bottom
TP401 "ADC_I1_INN" TP_SMD_1.2MM_ROUND#2 1608.14,185.04 r0 bottom
TVS300 "SRV05-4.TCT" SOT95P280X145-6N 1208.27,2615.35 r180 top
TVS301 "SRV05-4.TCT" SOT95P280X145-6N 708.27,2615.35 r180 top
TVS302 "SRV05-4.TCT" SOT95P280X145-6N 1208.27,3027.17 r180 top
TVS303 "SRV05-4.TCT" SOT95P280X145-6N 716.14,3027.17 r180 top
XTL200 "25MHz" FOX924B-25.000 1092.68,2282.34 r180 top

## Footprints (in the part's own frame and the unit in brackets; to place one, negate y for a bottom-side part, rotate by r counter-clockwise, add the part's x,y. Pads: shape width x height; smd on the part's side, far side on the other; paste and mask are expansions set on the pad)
C0603 [mm] "0603 ceramic capacitor"
  rect 1x1.1 smd: 1(-0.85,0) 2(0.85,0)
  body extent -0.8,-0.4 0.8,0.4, height 0.8
C1206 [mm] "1206 ceramic capacitor"
  rect 1.1x1.8 smd: 1(-1.5,0) 2(1.5,0)
  body extent -1.6,-0.8 1.6,0.8, height 0.76
C1210 [mm] "1210 capacitor"
  rect 1.1x2.8 smd: 1(-1.5,0) 2(1.5,0)
  body extent -1.6,-1.25 1.6,1.25, height 0.77
"CON, TMC Debug SPI" [mm]
  rect 0.6x1.6 smd: 1(-2,2.8) 2(-2,-2.8) 3(-1,2.8) 4(-1,-2.8) 5(0,2.8) 6(0,-2.8) 7(1,2.8) 8(1,-2.8) 9(2,2.8) 10(2,-2.8)
  rect 0.85x1.8 smd: 11(-3.325,0.4) 12(3.325,0.4)
  silkscreen extent -3.67,-2.75 3.68,2.7, body extent -3.65,-3.23 3.65,3.17, height 4.6
FOX924B-25.000 [mm] "TCXO, 25 MHz, 2.5 ppm, SMD, 5mm x 3.2mm, HCMOS, 3.3 V, FOX924 Series"
  rect 1.6x1.3 smd: 1(-2.003,-1.25) 2(2.003,-1.25) 3(2.003,1.25) 4(-2.003,1.25)
  silkscreen extent -3,-2.64 3,2.1, body extent -2.5,-1.6 2.5,1.6, height 1.51
Interface_Connector [mil]
  rect 40x75 smd: 1(-1050,122.72) 2(-1050,-122.72) 3(-950,122.72) 4(-950,-122.72) 5(-850,122.72) 6(-850,-122.72) 7(-750,122.72) 8(-750,-122.72) 9(-650,122.72) 10(-650,-122.72) 11(-550,122.72) 12(-550,-122.72) 13(-450,122.72) 14(-450,-122.72) 15(-350,122.72) 16(-350,-122.72) 17(-250,122.72) 18(-250,-122.72) 19(-150,122.72) 20(-150,-122.72) 21(-50,122.72) 22(-50,-122.72) 23(50,122.72) 24(50,-122.72) 25(150,122.72) 26(150,-122.72) 27(250,122.72) 28(250,-122.72) 29(350,122.72) 30(350,-122.72) 31(450,122.72) 32(450,-122.72) 33(550,122.72) 34(550,-122.72) 35(650,122.72) 36(650,-122.72) 37(750,122.72) 38(750,-122.72) 39(850,122.72) 40(850,-122.72) 41(950,122.72) 42(950,-122.72) 43(1050,122.72) 44(1050,-122.72)
  round 44 hole 44: HOLE(-1050,-50.28) HOLE(-1050,49.72) HOLE(-950,-50.28) HOLE(-950,49.72) HOLE(-850,-50.28) HOLE(-850,49.72) HOLE(-750,-50.28) HOLE(-750,49.72) HOLE(-650,-50.28) HOLE(-650,49.72) HOLE(-550,-50.28) HOLE(-550,49.72) HOLE(-450,-50.28) HOLE(-450,49.72) HOLE(-350,-50.28) HOLE(-350,49.72) HOLE(-250,-50.28) HOLE(-250,49.72) HOLE(-150,-50.28) HOLE(-150,49.72) HOLE(-50,-50.28) HOLE(-50,49.72) HOLE(50,-50.28) HOLE(50,49.72) HOLE(150,-50.28) HOLE(150,49.72) HOLE(250,-50.28) HOLE(250,49.72) HOLE(350,-50.28) HOLE(350,49.72) HOLE(450,-50.28) HOLE(450,49.72) HOLE(550,-50.28) HOLE(550,49.72) HOLE(650,-50.28) HOLE(650,49.72) HOLE(750,-50.28) HOLE(750,49.72) HOLE(850,-50.28) HOLE(850,49.72) HOLE(950,-50.28) HOLE(950,49.72) HOLE(1050,-50.28) HOLE(1050,49.72)
  round 71 hole 71: HOLE(-1000,-0.28) HOLE(1000,-0.28)
  silkscreen extent -1107,143 -1093,157, body extent -1100,-129 1100,130, height 144
L0603 [mm] "0603 inductor"
  rect 1x1.1 smd: 1(-0.85,0) 2(0.85,0)
  body extent -0.8,-0.5 0.8,0.45, height 0.79
MNT_HOLE_6.35-3.2 [mm]
  round 6.35 hole 3.2: 1(0,0)
  silkscreen extent -3.3,-3.3 3.3,3.3
QFN40P1050X650X90_HS-77N [mm] "QFN, 76-Leads, Body 10,50x6,50mm, Pitch 0,40mm, Thermal Pad 9,00x5,00mm, IPC Medium Density"
  oval 0.8x0.182 smd mask+0.051: 1(-5.15,2.6) 14(-5.15,-2.6) 39(5.15,-2.6) 52(5.15,2.6)
  oval 0.85x0.182 smd mask+0.051: 2(-5.15,2.2) 3(-5.15,1.8) 4(-5.15,1.4) 5(-5.15,1) 6(-5.15,0.6) 7(-5.15,0.2) 8(-5.15,-0.2) 9(-5.15,-0.6) 10(-5.15,-1) 11(-5.15,-1.4) 12(-5.15,-1.8) 13(-5.15,-2.2) 40(5.15,-2.2) 41(5.15,-1.8) 42(5.15,-1.4) 43(5.15,-1) 44(5.15,-0.6) 45(5.15,-0.2) 46(5.15,0.2) 47(5.15,0.6) 48(5.15,1) 49(5.15,1.4) 50(5.15,1.8) 51(5.15,2.2)
  oval 0.182x0.8 smd mask+0.051: 15(-4.6,-3.15) 38(4.6,-3.15) 53(4.6,3.15) 76(-4.6,3.15)
  oval 0.182x0.85 smd mask+0.051: 16(-4.2,-3.15) 17(-3.8,-3.15) 18(-3.4,-3.15) 19(-3,-3.15) 20(-2.6,-3.15) 21(-2.2,-3.15) 22(-1.8,-3.15) 23(-1.4,-3.15) 24(-1,-3.15) 25(-0.6,-3.15) 26(-0.2,-3.15) 27(0.2,-3.15) 28(0.6,-3.15) 29(1,-3.15) 30(1.4,-3.15) 31(1.8,-3.15) 32(2.2,-3.15) 33(2.6,-3.15) 34(3,-3.15) 35(3.4,-3.15) 36(3.8,-3.15) 37(4.2,-3.15) 54(4.2,3.15) 55(3.8,3.15) 56(3.4,3.15) 57(3,3.15) 58(2.6,3.15) 59(2.2,3.15) 60(1.8,3.15) 61(1.4,3.15) 62(1,3.15) 63(0.6,3.15) 64(0.2,3.15) 65(-0.2,3.15) 66(-0.6,3.15) 67(-1,3.15) 68(-1.4,3.15) 69(-1.8,3.15) 70(-2.2,3.15) 71(-2.6,3.15) 72(-3,3.15) 73(-3.4,3.15) 74(-3.8,3.15) 75(-4.2,3.15)
  rect 9x5 smd: 77(0,0)
  silkscreen extent -6.17,-3.4 5.4,3.4, body extent -5.25,-3.25 5.25,3.25, height 0.9
R0603 [mm] "0603 resistor"
  rect 1x1.1 smd: 1(-0.85,0) 2(0.85,0)
  body extent -0.8,-0.4 0.8,0.4, height 0.45
R0805 [mm] "0805 resistor"
  rect 1x1.4 smd: 1(-1,0) 2(1,0)
  body extent -1,-0.62 1,0.62, height 0.6
SOP127P600X175-8N [mm] "SOP, 8-Leads, Body 4,92x3,90mm, Pitch 1,27mm, IPC Medium Density"
  oval 1.45x0.6 smd: 1(-2.725,1.905) 2(-2.725,0.635) 3(-2.725,-0.635) 4(-2.725,-1.905) 5(2.725,-1.905) 6(2.725,-0.635) 7(2.725,0.635) 8(2.725,1.905)
  silkscreen extent -2.85,-2.55 1.6,2.88, body extent -3,-2.55 3,2.55, height 1.75
SOT95P237X130-3N [mm] "SOT23, 3-Leads, Body 2,90x2,37mm, Pitch 0,95mm, IPC Medium Density"
  rect 0.95x0.6 smd: 1(-1.225,0.95) 2(-1.225,-0.95) 3(1.225,0)
  silkscreen extent -1.35,-1.55 0.75,1.92, body extent -1.32,-1.55 1.32,1.55, height 1.3
SOT95P280X145-6N [mm] "SOT23, 6-Leads, Body 2,95x2,80mm, Pitch 0,95mm, IPC Medium Density"
  rect 0.95x0.6 smd: 1(-1.35,0.95) 2(-1.35,0) 3(-1.35,-0.95) 4(1.35,-0.95) 5(1.35,0) 6(1.35,0.95)
  silkscreen extent -1.48,-1.55 0.5,1.92, body extent -1.4,-1.55 1.4,1.55, height 1.45
SOT230P700X180-4N [mm] "SOT223, 4-Leads, Body 6,50x7,00mm (avg), Pitch 2,30mm, IPC Medium Density"
  rect 2.15x0.9 smd: 1(-2.925,2.3) 2(-2.925,0) 3(-2.925,-2.3)
  rect 2.15x3.25 smd: 4(2.925,0)
  silkscreen extent -3.05,-3.35 1.55,3.42, body extent -3.5,-3.35 3.5,3.35, height 1.8
TH_HDR_1X2 [mil]
  oval 60x98.43 hole 40: 1(-50,0) 2(50,0)
  silkscreen extent -100,-50 100,50, body extent -100,-50 100,50, height 351
TH_HDR_1X3 [mil]
  oval 60x98.43 hole 40: 1(-100,0) 2(0,0) 3(100,0)
  silkscreen extent -150,-50 150,50, body extent -150,-50 150,50, height 351
TH_HDR_1X5 [mil]
  oval 60x98.43 hole 40: 1(-200,0) 2(-100,0) 3(0,0) 4(100,0) 5(200,0)
  silkscreen extent -250,-50 250,50, body extent -250,-50 250,50, height 351
TMC4671_EVAL_V1_0_BACK_LABEL [mil]
  silkscreen extent -591,0 591,2087
TMC_logo_small [mil]
  silkscreen extent -193,-188 193,62
TP_1.1-1.85_OCT [mm]
  oct 1.85x1.85 hole 1.1: 1(0,0)
  silkscreen extent -1.27,-1.27 1.27,1.27
TP_SMD_1.2MM_ROUND#1 [mm]
  rrect100% 1.2x1.2 smd: 1(0,1.69)
TP_SMD_1.2MM_ROUND#2 [mm]
  rrect100% 1.2x1.2 smd: 1(0,0)
TSSOP50P310X90-8L [mm] "TSSOP, 8-Leads, Body 2,00x2,30mm, Pitch 0,50mm, IPC High Density"
  oval 0.6x0.25 smd: 1(-1.5,0.75) 2(-1.5,0.25) 3(-1.5,-0.25) 4(-1.5,-0.75) 5(1.5,-0.75) 6(1.5,-0.25) 7(1.5,0.25) 8(1.5,0.75)
  silkscreen extent -1.63,-1.05 0.8,1.55, body extent -1.55,-1.05 1.55,1.05, height 0.9

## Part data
C200 C201 C304 C305 C306 C307 C320 C321 C322 C323 C601 C602 C604 C605 C606 C607 C608 C610: library part "C, 0.1 µF, 10 V, ± 10%, X7R, 0603", "SMD Multilayer Ceramic Capacitor, 0603 [1608 Metric], 0.1 µF, 10 V, ± 10%, X7R, MC Series", Capacitance=100nF, MPN=MC0603B104K100CT, VoltageRating=10V
C300 C301 C302 C303 C500: library part "C, 1 µF, 10 V, ± 10%, X5R, MC Series, 0603 [1608 Metric]", "SMD Multilayer Ceramic Capacitor, 0603 [1608 Metric], 1 µF, 10 V, ± 10%, X5R, MC Series", Capacitance=1uF, MPN=MC0603X105K100CT, VoltageRating=10V
C308 C309 C310 C311 C312 C313 C314 C315 C316 C317 C318 C319 C501 C502 C503 C504 C505: library part "C, 100 pF, 50 V, ± 5%, C0G / NP0, MC Series, 0603 [1608 Metric]", "SMD Multilayer Ceramic Capacitor, 0603 [1608 Metric], 100 pF, 50 V, ± 5%, C0G / NP0, MC Series", Capacitance=100pF, MPN=MC0603N101J500CT, VoltageRating=50V
C506 C507: library part "C, 100 pF, 10 V, ± 1%, C0G / NP0, MCMT Series, 0603 [1608 Metric]", "SMD Multilayer Ceramic Capacitor, 0603 [1608 Metric], 100 pF, 10 V, ± 1%, C0G / NP0, MCMT Series", Capacitance=100pF, MPN=MCMT18N101F100CT, VoltageRating=10V
C508: library part "C, 10nF, 10 V, ± 10%, X7R, 0603", "SMD Multilayer Ceramic Capacitor, 0603 [1608 Metric], 0.01 µF, 10 V, ± 10%, X7R, MCSH Series", MPN=MCSH18B103K100CT, VoltageRating=10V
C600: library part "C, 100 µF, 16 V, ± 20%, X5R, M Series, 1210", "SMD Multilayer Ceramic Capacitor, 1210 [3225 Metric], 100 µF, 16 V, ± 20%, X5R, M Series", Capacitance=100uF, MPN=EMK325ABJ107MM-T, VoltageRating=16V
C603 C609: library part "C, 4.7 µF, 10 V, ± 10%, X5R, MC Series , 0603", "SMD Multilayer Ceramic Capacitor, 0603 [1608 Metric], 4.7 µF, 10 V, ± 10%, X5R, MC Series", Capacitance=4u7, MPN=MC0603X475K100CT, VoltageRating=10V
C611: library part "C, 100 µF, 6.3 V, ± 20%, X5R, GRM Series, 1210", "SMD Multilayer Ceramic Capacitor, 1210 [3225 Metric], 100 µF, 6.3 V, ± 20%, X5R, GRM Series", Capacitance=100uF, MPN=GRM31CR60J107ME39L., VoltageRating=6V3
C612: library part "C, 47 µF, 10 V, ± 20%, X7R, MC Series , 1206", "SMD Multilayer Ceramic Capacitor, 1206 [3216 Metric], 47 µF, 10 V, ± 20%, X5R, GRM Series", Capacitance=47uF, MPN=GRM31CR61A476ME15L, VoltageRating=10V
C613: library part "C, 0.1 µF, 10 V, ± 10%, X7R, 0603", "SMD Multilayer Ceramic Capacitor, 0603 [1608 Metric], 0.1 µF, 10 V, ± 10%, X7R, MC Series", MPN=MC0603B104K100CT, VoltageRating=10V
C614: library part "C, 0.47 µF, 16 V, ± 10%, X5R, MC Series, 0603 [1608 Metric]", "SMD Multilayer Ceramic Capacitor, 0603 [1608 Metric], 0.47 µF, 16 V, ± 10%, X5R, MC Series", MPN=MC0603X474K160CT, Voltage rating=16V
C615: library part "C, 4.7 µF, 10 V, ± 10%, X5R, MC Series , 0603", "SMD Multilayer Ceramic Capacitor, 0603 [1608 Metric], 4.7 µF, 10 V, ± 10%, X5R, MC Series", MPN=MC0603X475K100CT, VoltageRating=10V
D200 D500 D501 D502 D503 D504 D505: "Small Signal Schottky Diode, Dual Series, 30 V, 200 mA, 1 V, 600 mA, 125 °C"
IC201: library part "EEPROM_ AT25128B-SSHL-T", "EEPROM, SPI, 128 Kbit, 16K x 8bit, 20 MHz, SOIC, 8 Pins"
IC300 IC301 IC302 IC303: "Triple Schmitt-Trigger Buffer, 74LVC3G17, 1.65 V to 5.5 V, VSSOP-8"
IC600: library part LDO_LD1117S33CTR, "Fixed LDO Voltage Regulator, 4.75V to 15V, 1.1V Dropout, 3.3Vout, 950mAout, SOT-223-4"
L200: library part "FB, 30 ohm, 0603 [1608 Metric], MFB Series, 3 A, 0.04 ohm, ± 25%", "Ferrite Bead, 30 ohm, 0603 [1608 Metric], MFB Series, 3 A, 0.04 ohm, ± 25%", DC Current Rating=3A, DC Resistance Max=0R04, MPN=MFB-160808-0030PQ, Tolerance=±25%
P1 P2: library part "Interface Connector, 44 Pins", "Board-To-Board Connector, 2.54 mm, 44 Contacts, Receptacle, HLE Series, Surface Mount, 2 Rows", MPN=HLE-122-02-L-DV
P200: library part "Header 3", "Header, 3-Pin"
P201: library part "CON, TMC Debug SPI", "Wire-To-Board Connector, 1 mm, 10 Contacts, Header, DF20 Series, Surface Mount, 2 Rows"
P202 P400 P501 P502: library part "Header 2", "Header, 2-Pin"
P300 P301 P302 P303 P500: library part "Header 5", "Header, 5-Pin"
PIN1 PIN2 PIN3 PIN4: library part TP_1.1-1.85_OCT, "TH testpoint, 1.1 hole, 1.85 pad, octagonal"
R200 R400 R401 R402 R403 R404 R405 R407 R408 R409 R410: library part "R, 10 kohm, 50 V, 0603 [1608 Metric], 63 mW, ± 1%, MC Series", "SMD Chip Resistor, Thick Film, 10 kohm, 50 V, 0603 [1608 Metric], 63 mW, ± 1%, MC Series", MPN=MC0063W0603110K, PowerRating=63mW, Temp coefficient=*ppm, VoltageRating=50V
R300 R301 R302 R303 R304 R305 R306 R307 R308 R309 R310 R311: library part "R, 22 ohm, 50 V, 0603 [1608 Metric], 100 mW, ± 1%, MCWR Series", "SMD Chip Resistor, Thick Film, 22 ohm, 50 V, 0603 [1608 Metric], 100 mW, ± 1%, MCWR Series", MPN=MCWR06X22R0FTL, PowerRating=100mW, Temp coefficient=*ppm, VoltageRating=50V
R312 R313 R314 R315 R316 R317 R318 R319 R320 R321 R322 R323: library part "R, 4.7 kohm, 75 V, 0603 [1608 Metric], 100 mW, ± 1%, WR06 Series", "SMD Chip Resistor, 4.7 kohm, 75 V, 0603 [1608 Metric], 100 mW, ± 1%, WR06 Series", MPN=WR06X4701FTL, PowerRating=100mW, Temp coefficient=*ppm, VoltageRating=75V
R406: library part "R, 10 ohm, 50 V, 0603 [1608 Metric], 100 mW, ± 1%, MCWR Series", "SMD Chip Resistor, Thick Film, 10 ohm, 50 V, 0603 [1608 Metric], 100 mW, ± 1%, MCWR Series", MPN=MC0063W0603110K, PowerRating=100mW, Temp coefficient=*ppm, VoltageRating=50V
R500 R501 R502 R503 R504: library part "R, 100 ohm, 50 V, 0603 [1608 Metric], 100 mW, ± 1%, MCWR Series", "SMD Chip Resistor, Thick Film, 100 ohm, 50 V, 0603 [1608 Metric], 100 mW, ± 1%, MCWR Series", MPN=MCWR06X1000FTL, PowerRating=100mW, Temp coefficient=*ppm, VoltageRating=50V
R505 R506: library part "R, 4 kohm, 150 V, 0805 [2012 Metric], 125 mW, ± 1%, CRCW Series", "SMD Chip Resistor, Thick Film, 4 kohm, 150 V, 0805 [2012 Metric], 125 mW, ± 1%, CRCW Series", MPN=CRCW08054K00FKTA, PowerRating=125mW, Temp coefficient=*ppm, VoltageRating=150V
R507 R508: library part "R, 1 kohm, 50 V, 0603 [1608 Metric], 63 mW, ± 1%, MC Series", "SMD Chip Resistor, Thick Film, 1 kohm, 50 V, 0603 [1608 Metric], 100 mW, ± 0.5%, RE Series", MPN=MC0063W060311K, PowerRating=63mW, Temp coefficient=*ppm, VoltageRating=50V
R509: library part "R, 1.5 kohm, 50 V, 0603 [1608 Metric], 100 mW, ± 1%, MCWR Series", "SMD Chip Resistor, Thick Film, 1.5 kohm, 50 V, 0603 [1608 Metric], 100 mW, ± 1%, MCWR Series", MPN=MCWR06X1501FTL, PowerRating=63mW, Temp coefficient=*ppm, VoltageRating=50V
R510: library part "R, 100 kohm, 50 V, 0603 [1608 Metric], 100 mW, ± 1%, MCWR Series", "SMD Chip Resistor, Thick Film, 100 kohm, 50 V, 0603 [1608 Metric], 100 mW, ± 1%, MCWR Series", MPN=MCWR06X1003FTL, Temp coefficient=*ppm
SILK1 SILK2: library part SILK_GFX
TP1 TP2 TP3 TP4 TP5 TP6 TP7 TP8 TP9 TP10 TP11 TP12 TP13 TP14 TP400 TP401: library part TP_SMD_Xmm, "SMD testpoint, 1.2mm pad, round"
TVS300 TVS301 TVS302 TVS303: library part "ESD, TVS, SRV05-4.TCT", "ESD Protection Device, TVS, 17.5 V, SOT-23, 6 Pins, 5 V, 300 W"
XTL200: library part "25 MHz, 2.5 ppm, SMD, 5mm x 3.2mm, HCMOS, 3.3 V, FOX924 Series", "TCXO, 25 MHz, 2.5 ppm, SMD, 5mm x 3.2mm, HCMOS, 3.3 V, FOX924 Series", Freq. Stability=2.5ppm, MPN=FOX924B-25.000, Op.temp.=-30°C...+80°C

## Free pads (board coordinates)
  round 0 on Mech16 paste+0 mask+0: 1(1296.85,1913.39) 1(1296.85,1956.69)

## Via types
v1: diameter 24, hole 12, Top to Bottom, tented both sides, 171 vias
v2: diameter 20, hole 10, Top to Bottom, tented both sides, 136 vias
v3: diameter 24.1, hole 12, Top to Bottom, tented both sides, 67 vias
v4: diameter 24, hole 10, Top to Bottom, 32 vias
v5: diameter 26, hole 14, Top to Bottom, tented both sides, 7 vias
v6: diameter 32, hole 16, Top to Bottom, tented both sides, 6 vias
v7: diameter 39.37, hole 23.62, Top to Bottom, tented both sides, 2 vias
v8: diameter 50, hole 40, Top to Bottom, tented both sides, 2 vias

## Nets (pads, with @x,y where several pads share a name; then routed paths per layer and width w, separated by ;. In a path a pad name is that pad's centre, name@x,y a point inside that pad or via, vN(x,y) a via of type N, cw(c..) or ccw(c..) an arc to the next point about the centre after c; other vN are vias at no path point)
+3V3: C201.2 C320.2 C321.2 C322.2 C323.2 C601.2 C604.2 C606.2 C608.2 C609.2 C610.2 C611.2 C612.2 C613.2 C614.1 D200.2 IC200.2 IC200.13 IC200.43 IC200.52 IC200.61 IC200.72 IC201.3 IC201.8 IC300.8 IC301.8 IC302.8 IC303.8 IC600.2 IC600.4 L200.1 P201.1 R200.2 TP1.1 | length 1710.8
  Top w7.1: 934.84,1568.39 IC200.72@958.66,1568.39 ; 940.94,1741.62 IC200.61@958.66,1741.62 ; 996.06,1457.76 IC200.2@996.06,1483.74 ; IC200.43@1122.05,1889.26 1122.05,1913.17 ; 1169.29,1459.45 IC200.13@1169.29,1471.01
  Top w10: IC200.52@978.76,1889.26 C613.2@978.76,1928.88
  Top w11.81: v5@918.66,1741.62 936.64,1741.62 ; v5@922.68,1561.5 v5@928.57,1567.39 ; v5@923.47,1567.39 v5@928.57,1567.39 ; 934.84,1567.39 v5@928.57,1567.39 ; 980.76,1444.45 994.06,1457.76 ; 1122.05,1913.17 v5@1122.05,1941.82 ; 1171.29,1457.16 1185.99,1442.46 v5(1185.99,1438.62)
  Top w12: IC201.3@339.01,365.94 393.12,365.94 v6(393.7,365.35) ; v6(539.19,589.54) 539.98,588.75 C201.2@539.98,538.36 553.58,524.76 IC201.8@553.58,465.94 ; v1(826.58,1297.29) P201.1@826.58,1348.47 ; v1(1051.46,2105.53) L200.1@1088.86,2105.53 ; R200.2@1121.1,2041.89 v1(1158.5,2041.89)
  Top w20: v6(958.94,2134.23) 959.96,2133.21 C612.2@959.96,2073.62 ; C613.2@962.57,1942.37 C614.1@962.57,2002.37 C612.2@962.57,2074.48
  Bottom w10: v1(700.39,2912.99) 702.36,2914.96 C323.2@702.36,2960.24 724.02,2981.89 IC303.8@763.39,2981.89 ; C321.2@719.6,2537.29 719.6,2560.2 729.4,2570 763.31,2570 IC301.8@763.39,2570.08 ; v1(1179.06,2915.65) 1181.73,2918.33 1181.73,2937.64 1217.05,2972.95 1217.05,2976.89 1221.97,2981.81 1263.31,2981.81 IC302.8@1263.39,2981.89 ; C320.2@1202.36,2548.43 1224.02,2570.08 IC300.8@1263.39,2570.08
  Bottom w11.81: v5@922.96,1741.62 v5(922.68,1741.34) 934.77,1753.43 958.23,1753.43 C601.2@972.68,1767.87 ; v5@923.68,1562.5 923.68,1566.87 941.4,1566.87 959.33,1584.8 C610.2@972.68,1584.8 ; v5(963.3,1442.1) 978.04,1442.1 C604.2@1009.84,1473.9 ; 1122.05,1918.78 1122.05,1897.13 C608.2@1135.83,1883.35 ; v5(1185.99,1438.62) 1185.99,1465.01 C606.2@1194.88,1473.9
  Bottom w12: TP1.1@366.14,185.04 366.14,345.67 385.83,365.35 v6(393.7,365.35) ; v1(704.91,2511.02) C321.2@704.91,2548.43 ; D200.2@754.94,1634.23 v1(792.34,1634.23) ; v1(1202.36,2511.02) C320.2@1202.36,2548.43
  other v1: 208.66,2922.83 208.66,2954.33 208.66,2985.83 208.66,3017.32
  other v5: 923.68,1560.5 1122.85,1935.62
+5V: C300.2 C301.2 C302.2 C303.2 C304.1 C305.1 C306.1 C307.1 C500.2 C600.2 C603.2 C615.2 D500.2 D501.2 D502.2 D503.2 D504.2 D505.2 IC200.23 IC600.3 P1.42 P2.42 P300.5 P301.5 P302.5 P303.5 P500.5 R312.2 R313.2 R314.2 R315.2 R316.2 R317.2 R318.2 R319.2 R320.2 R321.2 R322.2 R323.2 R400.2 R402.2 R404.2 R407.2 R409.2 TP2.1 TVS300.5 TVS301.5 TVS302.5 TVS303.5 | length 10135.2
  Top w7.1: IC200.23@1209.69,1631.38 1228.41,1631.38
  Top w11.81: 1231.51,1633.38 v5@1242.5,1633.38
  Top w12: v6@480.65,248.42 v6(480.85,248.62) ; v2@559.06,3056.69 C307.1@606.3,3056.69 635.83,3027.17 TVS303.5@662.99,3027.17 ; v2(596.94,2689.23) C305.1@596.94,2649.23 630.81,2615.35 TVS301.5@655.12,2615.35 ; D504.2@833.27,813.28 D504.2@841.14,813.28 v1(880.3,813.28) ; D505.2@975,813.28 D505.2@976.97,813.28 986.32,813.28 v1(1011.62,838.58) ; D502.2@1105.79,813.28 1117.11,813.28 v1(1142.4,838.58) ; v2(1145.28,2741.34) 1113.78,2709.84 1113.78,2661.42 C304.1@1097.24,2644.88 1126.77,2615.35 TVS300.5@1155.12,2615.35 ; v2(1145.28,3153.15) 1113.78,3121.65 1113.78,3073.23 C306.1@1097.24,3056.69 1126.77,3027.17 TVS302.5@1155.12,3027.17 ; v6(1230.68,374.96) 1230.68,412.5 C500.2@1232.68,414.49 ; D501.2@1237.68,813.28 1249,813.28 v1(1274.29,838.58) ; D500.2@1369.57,813.28 1380.89,813.28 v1(1406.18,838.58) ; R409.2@1470.63,1381.89 v1(1508.03,1381.89) ; R407.2@1470.63,1618.11 v1(1508.03,1618.11) ; R404.2@1470.63,1736.22 v1(1508.03,1736.22) ; R402.2@1470.63,1854.33 v1(1508.03,1854.33) ; R400.2@1470.63,1972.44 v1(1508.03,1972.44) ; D503.2@1501.46,813.29 1512.77,813.28 v1(1538.07,838.58)
  Top w39.37: P1.42@358.94,2623.23 v7(426.77,2623.23) 444.41,2640.87 C603.2@444.41,2755.65 IC600.3@444.41,2839.25
  Top w50: P2.42@2051.85,2633.86 v7(2051.85,2670.19)
  VM w12: v5(1243.16,1641.23) 1245,1641.23 1248.62,1644.85 1248.62,1665.42 1262.51,1679.31 1296.73,1679.31 1353.64,1736.22 v1(1508.03,1736.22) 1558.94,1736.22 ; v1(1508.03,1381.89) 1532.3,1357.62 ; v1@1513.94,1618.23 1542.76,1618.23 ; v1@1513.94,1854.45 1542.76,1854.45 ; v1@1513.94,1972.56 1542.76,1972.56 ; 1522.3,1357.62 1532.3,1357.62 ; 1535.85,1357.62 1532.3,1357.62
  VM w20: v6(480.85,248.62) 480.85,312.44 880.3,711.9 v1(880.3,813.28) 905.6,838.58 v1(1011.62,838.58) v1(1142.4,838.58) v1(1274.29,838.58) v1(1406.18,838.58) 1472.85,838.58 v1(1538.07,838.58)
  VM w50: v7(426.77,2623.23) 503.81,2623.23 632.68,2752.09 ; P301.5@632.68,2844.09 632.68,2752.09 ; P303.5@632.68,3255.91 632.68,3238.97 707.75,3163.91 1132.68,3163.91 ; P300.5@1132.68,2844.09 1132.68,2752.09 ; P302.5@1132.68,3255.91 1132.68,3163.91 ; P500.5@1182.68,314.96 1182.68,343.96 1472.85,634.13 1472.85,838.58 1472.85,1294.62 1535.85,1357.62 1563.94,1385.72 1563.94,2752.09 1689.1,2752.09 1732.28,2795.28 2009.45,2795.28 2052.76,2751.97 v7@2052.76,2670.19 ; 1501.57,3163.91 1132.68,3163.91 ; 1549.85,2752.09 1231.89,2752.09 1132.68,2752.09 ; 632.68,2752.09 645.28,2752.09 1132.68,2752.09
  Bottom w11.81: C615.2@1192.91,1645.16 1206.69,1631.38 v5@1240.16,1631.38
  Bottom w12: TP2.1@461.68,185.04 461.68,229.46 v6(480.85,248.62) ; v2(645.28,2741.34) 678.74,2741.34 C301.2@680.71,2739.37 ; C303.2@680.71,3151.18 682.68,3153.15 v2(682.68,3186.61) ; v2(731.89,2741.34) 765.35,2741.34 R313.2@767.32,2739.37 ; v2(731.89,3153.15) 765.35,3153.15 R315.2@767.32,3151.18 ; v2(860.85,3151.62) 897.68,3151.62 899.21,3153.15 R319.2@901.18,3151.18 ; v2(865.75,2741.34) 899.21,2741.34 R317.2@901.18,2739.37 ; v2(999.61,2741.34) 1033.07,2741.34 R321.2@1035.04,2739.37 ; v2(999.61,3153.15) 1033.07,3153.15 R323.2@1035.04,3151.18 ; v2(1145.28,2741.34) 1178.74,2741.34 C300.2@1180.71,2739.37 ; v2(1145.28,3153.15) 1178.74,3153.15 C302.2@1180.71,3151.18 ; v2(1231.89,2741.34) 1265.35,2741.34 R312.2@1267.32,2739.37 ; v2(1231.89,3153.15) 1265.35,3153.15 R314.2@1267.32,3151.18 ; v2(1365.75,2741.34) 1399.21,2741.34 R316.2@1401.18,2739.37 ; v2(1365.75,3153.15) 1399.21,3153.15 R318.2@1401.18,3151.18 ; v2(1499.61,2741.34) 1533.07,2741.34 R320.2@1535.04,2739.37 ; v2(1499.61,3153.15) 1533.07,3153.15 R322.2@1535.04,3151.18
  Bottom w50: P301.5@632.68,2844.09 543.31,2933.47 543.31,3166.54 P303.5@632.68,3255.91
  other v2: 559.06,3056.69
+5V_USB: P1.5 P2.5 | length 1768
  Top w10: P1.5@113.5,823.23 132.24,823.23 165.93,789.54 230.93,789.54 v2(231.85,788.62) ; v2(1746.85,823.62) 1747.24,823.23 P2.5@1806.41,823.23
  MID w10: v2(231.85,788.62) 233.45,790.23 408.45,790.23 432.45,814.23 804.59,814.23 860.2,758.62 1681.85,758.62 v2(1746.85,823.62)
+VCC_CORE: C602.2 C605.2 C607.2 IC200.15 IC200.45 IC200.63 | length 341.3
  Top w7.1: v1(914.62,1710.31) 914.75,1710.19 IC200.63@945.93,1710.19 ; IC200.45@1090.55,1893.26 1090.55,1910.97 1097.62,1918.04 ; 1094.3,1916.1 1094.3,1922.88 ; IC200.15@1206.69,1505.4 1224.41,1505.4 ; v1@909.76,1705.45 909.95,1705.45 914.62,1710.12 914.43,1710.12 v1@909.76,1705.45
  Top w11.81: 1096.71,1920.7 1096.71,1956.31 v1(1097.06,1956.65) ; 1224.41,1503 v5@1236.22,1503
  Bottom w11.81: v1(914.62,1710.31) 968.18,1710.31 C605.2@972.68,1714.8 ; C607.2@1084.65,1883.35 1097.06,1895.76 v1(1097.06,1956.65) ; C602.2@1192.91,1527.05 1206.97,1512.99 1228.63,1512.99 v5@1240.16,1501.46
  other v5: 1236.22,1497.4
+VM: P1.1 P2.1 R510.2 | length 2615.2
  Top w12: R510.2@1643.31,691.07 1711.15,623.23 P2.1@1806.41,623.23
  Top w80: v8(113.5,563.67) 113.5,602.36 ; 1807.09,598.43 1807.09,578.74 v8(1870.08,515.75)
  VM w80: v8(113.5,563.67) 113.5,465.24 417.32,161.42 1769.98,161.42 1870.08,261.52 v8(1870.08,515.75)
ADC_BIP: P2.36
ADC_I0_INN: IC200.17 R409.1 R410.2 TP400.1 | length 1710
  Top w7.1: IC200.17@1206.69,1536.89 1299.21,1536.89 R410.2@1393.7,1442.41
  Top w8: v2(1367.94,1375.23) 1403.7,1375.23 R409.1@1403.7,1381.89
  Top w12: R409.1@1403.7,1381.89 R410.2@1403.7,1440.95
  Bottom w8: v2(1367.94,1375.23) 1368.85,1374.32 1363.06,1368.53 1363.06,706.12 1538.94,530.24 1538.94,267.23 1570.94,235.23 1653.48,235.23 TP400.1@1703.67,185.04
ADC_I0_LP: C501.2 IC200.16 R500.1 | length 358.2
  Top w7.1: IC200.16@1206.69,1521.15 1245,1521.15 1342.52,1423.62 1342.52,1372.36 1392.05,1322.84 R500.1@1393.7,1322.84 ; C501.2@1403.7,1263.78 R500.1@1403.7,1322.84
ADC_I0_U: P2.15 R500.2 | length 335.8
  Top w12: R500.2@1470.63,1322.84 P2.15@1806.41,1322.84
ADC_I1_INN: IC200.19 R407.1 R408.2 TP401.1 | length 2069.2
  Top w7.1: IC200.19@1206.69,1568.39 1242.6,1568.39 1246.77,1564.23 1343.22,1564.23 1379.22,1600.23 1389.22,1600.23 1403.7,1614.7 R407.1@1403.7,1618.11 R408.2@1403.7,1677.16 1379.76,1653.23 v2(1368.94,1653.23)
  Bottom w8: v2(1368.94,1653.23) 1391.94,1630.23 1391.94,1573.35 1376.94,1558.35 1376.94,1432.65 1333.94,1389.65 1333.94,695.64 1438.94,590.64 1438.94,259.48 1464.94,233.48 1464.94,173.23 1496.94,141.23 1564.32,141.23 TP401.1@1608.14,185.04
ADC_I1_LP: C502.2 IC200.18 R501.1 | length 250.7
  Top w7.1: IC200.18@1206.69,1552.64 1206.8,1552.53 1239.94,1552.53 1242.24,1550.23 1384.87,1550.23 C502.2@1393.7,1559.06 ; R501.1@1403.7,1500 C502.2@1403.7,1559.06
ADC_I1_V: P2.14 R501.2 | length 695.9
  Top w8: R501.2@1470.63,1500 1580.71,1500 1708.09,1372.62 1881.85,1372.62 2031.24,1223.23 P2.14@2051.85,1223.23
ADC_I2_S: P2.16
ADC_START: P2.38
ADC_T_MOSFETS: P2.11
ADC_T_MOTOR: P2.12
ADC_U_UX: P2.41
ADC_U_V: P2.37
ADC_U_WY: P2.39
ADC_VM_LP: C508.2 D503.3 IC200.20 R509.1 R510.1 | length 1405.6
  Top w7.1: IC200.20@1206.69,1584.14 1245.38,1584.14 1251.29,1578.23 1321.45,1578.23 1336.45,1593.23 v2(1343.94,1593.23)
  Top w12: v2(1278.06,980.65) 1486.52,980.65 1584.94,882.23 1584.94,856.77 1591.02,850.69 D503.3@1597.91,850.69 1592.1,844.87 1592.1,764.98 C508.2@1585.12,758 ; R509.1@1583.15,693.04 C508.2@1583.15,756.03 C508.2@1585.12,758 ; R510.1@1643.31,758 C508.2@1585.12,758
  Bottom w8: v2(1278.06,980.65) 1291.94,994.54 1291.94,1407.05 1334.94,1450.05 1334.94,1580.98 1341.64,1587.69 1341.64,1595.52 v2@1340.49,1596.68 ; v2@1342.85,1599.03 1342.85,1594.32 v2(1343.94,1593.23)
AENC_UX: P500.3 R504.2 | length 486.7
  Top w12: R504.2@1120.55,693.04 1382.68,430.91 P500.3@1382.68,314.96
AENC_UX_INN: IC200.26 R404.1 R405.2 TP11.1 | length 1844.6
  Top w7.1: IC200.26@1206.69,1678.63 1336.11,1678.63 1376.71,1719.23 1386.71,1719.23 R404.1@1403.7,1736.22 R405.2@1403.7,1795.28
  Bottom w8: TP11.1@1321.52,185.04 1333.94,197.46 1333.94,656.04 1305.94,684.04 1305.94,1401.25 1348.94,1444.25 1348.94,1569.94 1363.94,1584.94 1363.94,1601.51 1334.94,1630.51 1334.94,1684.23 v2(1343.94,1693.23)
AENC_UX_LP: C505.2 D502.3 IC200.25 R504.1 | length 1084
  Top w7.1: IC200.25@1206.69,1662.88 1232.88,1662.88 1234.23,1664.23 1262.71,1664.23 v2(1270.62,1656.31)
  Top w12: R504.1@1187.48,693.04 C505.2@1187.48,756.03 1187.48,835.92 D502.3@1202.24,850.69 v2(1202.24,948.62)
  Bottom w8: v2(1202.24,948.62) 1202.24,981.84 1249.94,1029.54 1249.94,1424.44 1292.94,1467.44 1292.94,1633.81 1270.62,1656.13 v2(1270.62,1656.31)
AENC_VN: P500.2 R503.2 | length 473.4
  Top w12: R503.2@1252.44,693.04 1482.68,462.8 P500.2@1482.68,314.96
AENC_VN_INN: IC200.28 R402.1 R403.2 TP12.1 | length 1992.2
  Top w7.1: IC200.28@1219.43,1710.12 1266.5,1710.12 1278.19,1721.81 1308.03,1721.81 v2(1329.85,1743.62) 1346.77,1760.55 1346.77,1807.4 1375.6,1836.23 1385.6,1836.23 R402.1@1403.7,1854.33 R403.2@1403.7,1913.39
  Bottom w8: v2(1329.85,1743.62) 1363.94,1709.53 1363.94,1684.94 1348.94,1669.94 1348.94,1636.31 1377.94,1607.31 1377.94,1579.15 1362.94,1564.15 1362.94,1438.45 1319.94,1395.45 1319.94,689.84 1424.94,584.84 1424.94,192.92 TP12.1@1417.06,185.04
AENC_VN_LP: C504.2 D501.3 IC200.27 R503.1 | length 1188.3
  Top w7.1: IC200.27@1206.69,1694.37 1280.69,1694.37 v2(1287.62,1701.31)
  Top w12: v2(1241.06,949.65) 1247.45,949.65 1256.06,941.05 1256.06,940.54 1268.94,927.65 1269.45,927.65 1321.06,876.05 1321.06,856.87 1327.24,850.69 D501.3@1334.13,850.69 ; R503.1@1319.37,693.04 C504.2@1319.37,756.03 1319.37,835.92 D501.3@1334.13,850.69 ; D501.3@1328.32,844.87 D501.3@1334.13,850.69
  Bottom w8: v2(1241.06,949.65) 1241.06,994.65 1263.94,1017.54 1263.94,1418.64 1306.94,1461.64 1306.94,1681.99 v2(1287.62,1701.31)
AENC_WY: P500.1 R502.2 | length 460.2
  Top w12: R502.2@1384.33,693.04 1582.68,494.69 P500.1@1582.68,314.96
AENC_WY_INN: IC200.30 R400.1 R401.2 TP13.1 | length 2165
  Top w7.1: IC200.30@1206.69,1741.62 1258.39,1741.62 1282.78,1766 1308.63,1766 v2@1308.85,1766.22 ; v2(1308.85,1760.62) v2@1308.85,1766.22 ; R401.2@1403.7,2031.49 R400.1@1403.7,1972.44 1369.75,1938.49 1369.75,1861.01 1323.94,1815.2 1323.94,1773.23 1316.93,1766.22 v2@1308.85,1766.22
  Bottom w8: v2(1308.85,1760.62) 1311.14,1762.92 1320.86,1762.92 1321.56,1763.62 1338.13,1763.62 1405.94,1695.81 1405.94,1567.55 1390.94,1552.55 1390.94,1426.85 1347.94,1383.85 1347.94,701.44 1522.68,526.7 1522.68,279.18 1512.6,269.1 TP13.1@1512.6,185.04
AENC_WY_LP: C503.2 D500.3 IC200.29 R502.1 | length 1314.3
  Top w7.1: IC200.29@1219.43,1725.87 1262.45,1725.87 1279.89,1743.31 v2(1288.62,1743.31)
  Top w12: v2(1278.06,949.65) 1381.52,949.65 1452.94,878.23 D500.3@1452.94,856.88 ; R502.1@1451.26,693.04 C503.2@1451.26,756.03 1451.26,835.92 D500.3@1466.02,850.69 D500.3@1459.13,850.69
  Bottom w8: v2(1278.06,949.65) 1258.06,969.65 1258.06,988.94 1277.94,1008.82 1277.94,1412.84 1320.94,1455.84 1320.94,1710.99 v2(1288.62,1743.31)
AGPI_A: P502.1 R505.2 | length 302.3
  Top w12: P502.1@782.68,314.96 782.68,421.85 R505.2@920.87,560.04
AGPI_A_LP: C506.2 D504.3 IC200.21 R505.1 R507.1 | length 1234.7
  Top w7.1: IC200.21@1206.69,1599.89 1206.8,1599.78 1257.39,1599.78 v2(1258.94,1598.23)
  Top w12: R505.1@920.87,638.78 920.87,834.65 D504.3@937.6,851.38 ; D504.3@937.6,850.69 D504.3@937.6,851.38 ; v2(1066.85,953.62) 986.6,953.62 937.6,904.62 D504.3@937.6,851.38
  Bottom w8: v2(1066.85,953.62) 1117.41,953.62 1221.94,1058.15 1221.94,1436.04 1264.94,1479.04 1264.94,1592.23 v2(1258.94,1598.23)
AGPI_B: P501.1 R506.2 | length 276.9
  Top w12: P501.1@982.68,314.96 982.68,483.27 R506.2@1059.45,560.04
AGPI_B_LP: C507.2 D505.3 IC200.22 R506.1 R508.1 | length 1177
  Top w7.1: IC200.22@1206.69,1615.63 1248.06,1615.63 1250.66,1618.23 1260.48,1618.23 1268.73,1626.49 v2(1271.98,1626.49)
  Top w12: R506.1@1059.45,638.78 1059.45,834.65 D505.3@1076.18,851.38 ; D505.3@1073.43,850.69 1062.85,861.27 1062.85,896.62 1088.85,922.62 1114.7,922.62 v2(1141.85,949.77)
  Bottom w8: v2(1141.85,949.77) 1235.94,1043.86 1235.94,1430.24 1278.94,1473.24 1278.94,1619.53 v2(1271.98,1626.49)
AIN1: P1.15
BRAKE: IC200.31 R406.2 | length 1775.9
  Top w7.1: IC200.31@1206.69,1757.37 1254.34,1757.37 1286.29,1789.31 v2(1296.62,1789.31)
  Bottom w8: v2(1296.62,1789.31) 1332.24,1789.31 1419.94,1701.61 1419.94,1561.75 1404.94,1546.75 1404.94,1383.68 1377.06,1355.79 1377.06,711.92 1586.61,502.36 1748.87,502.36 1780.71,470.52 R406.2@1782.68,470.52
